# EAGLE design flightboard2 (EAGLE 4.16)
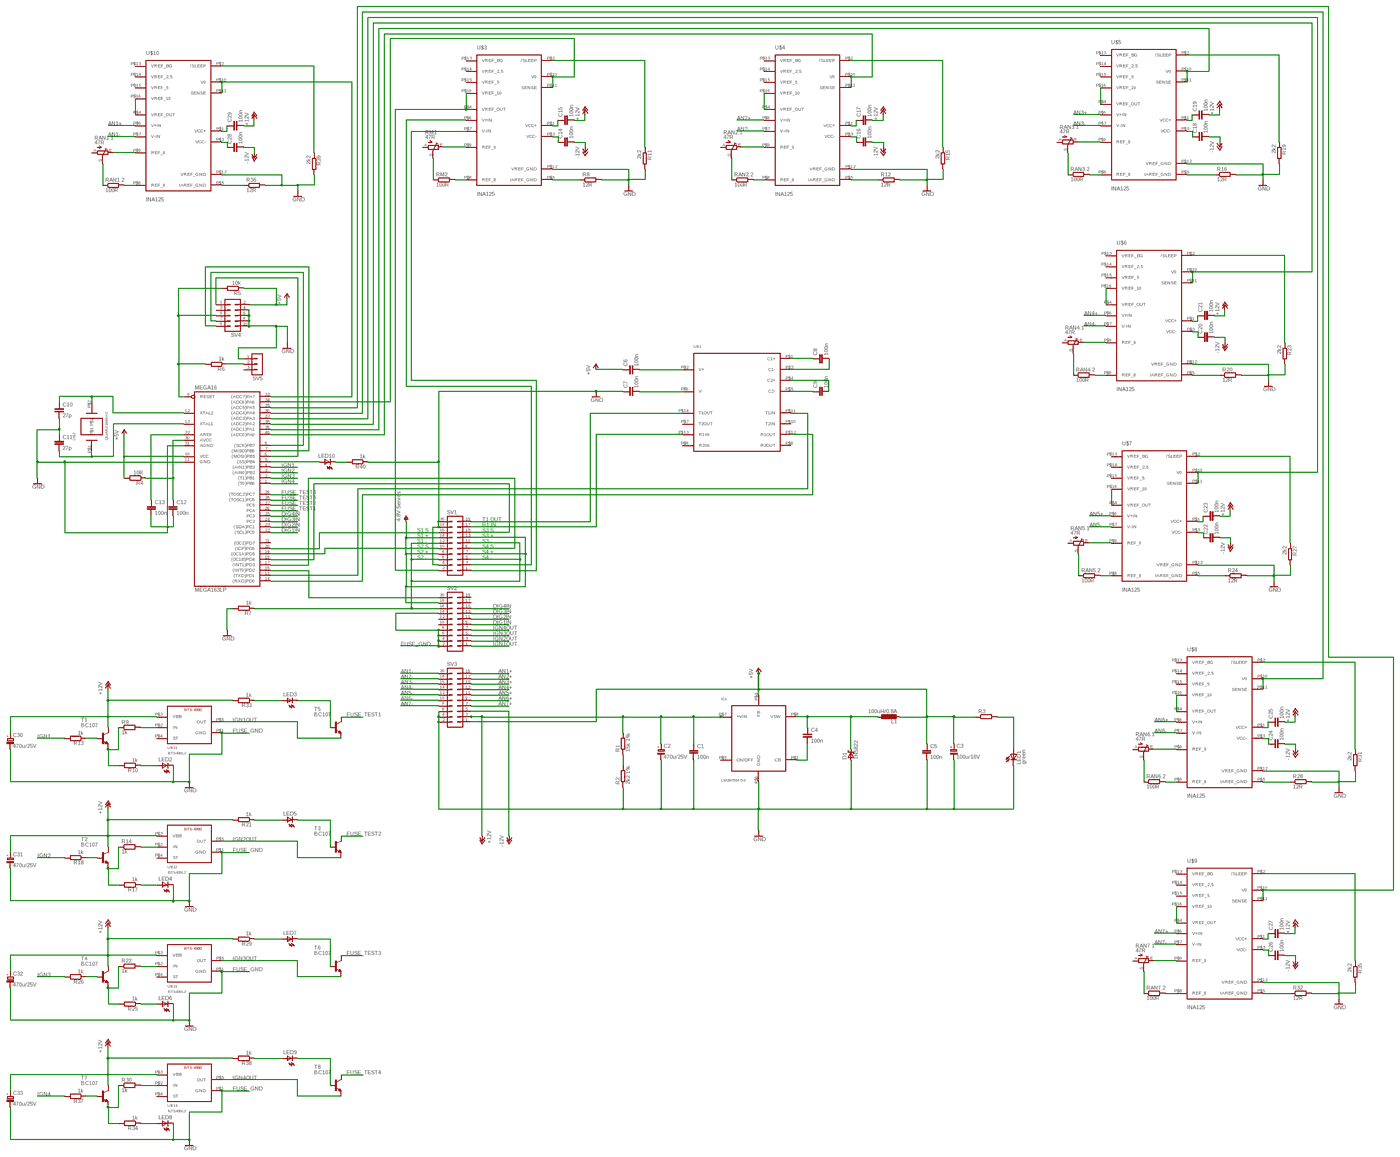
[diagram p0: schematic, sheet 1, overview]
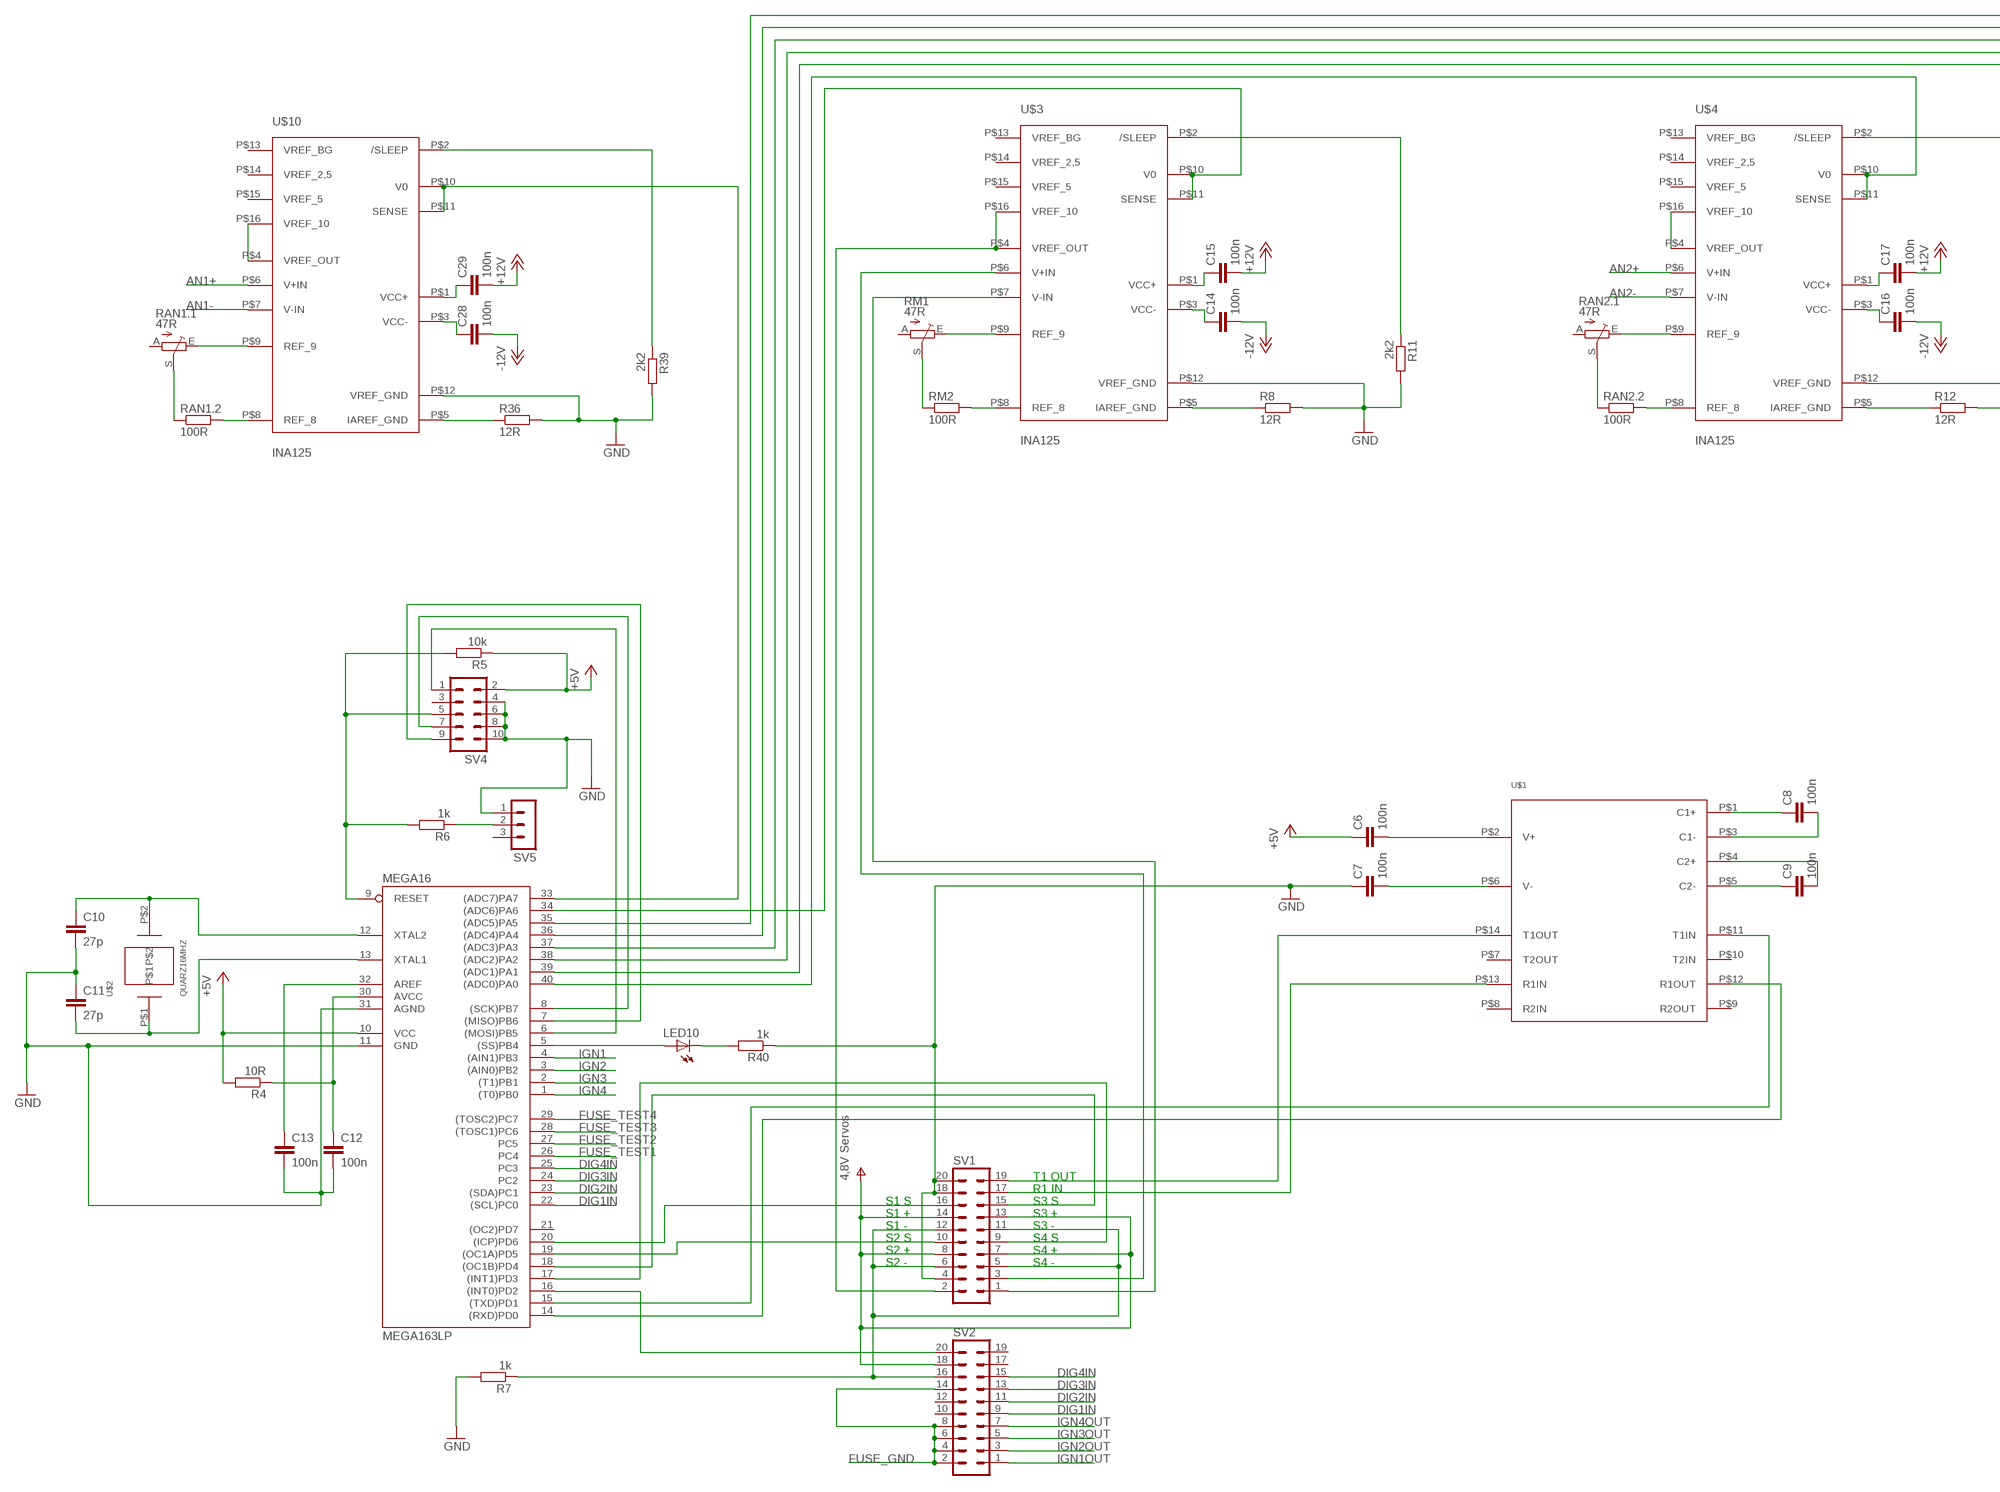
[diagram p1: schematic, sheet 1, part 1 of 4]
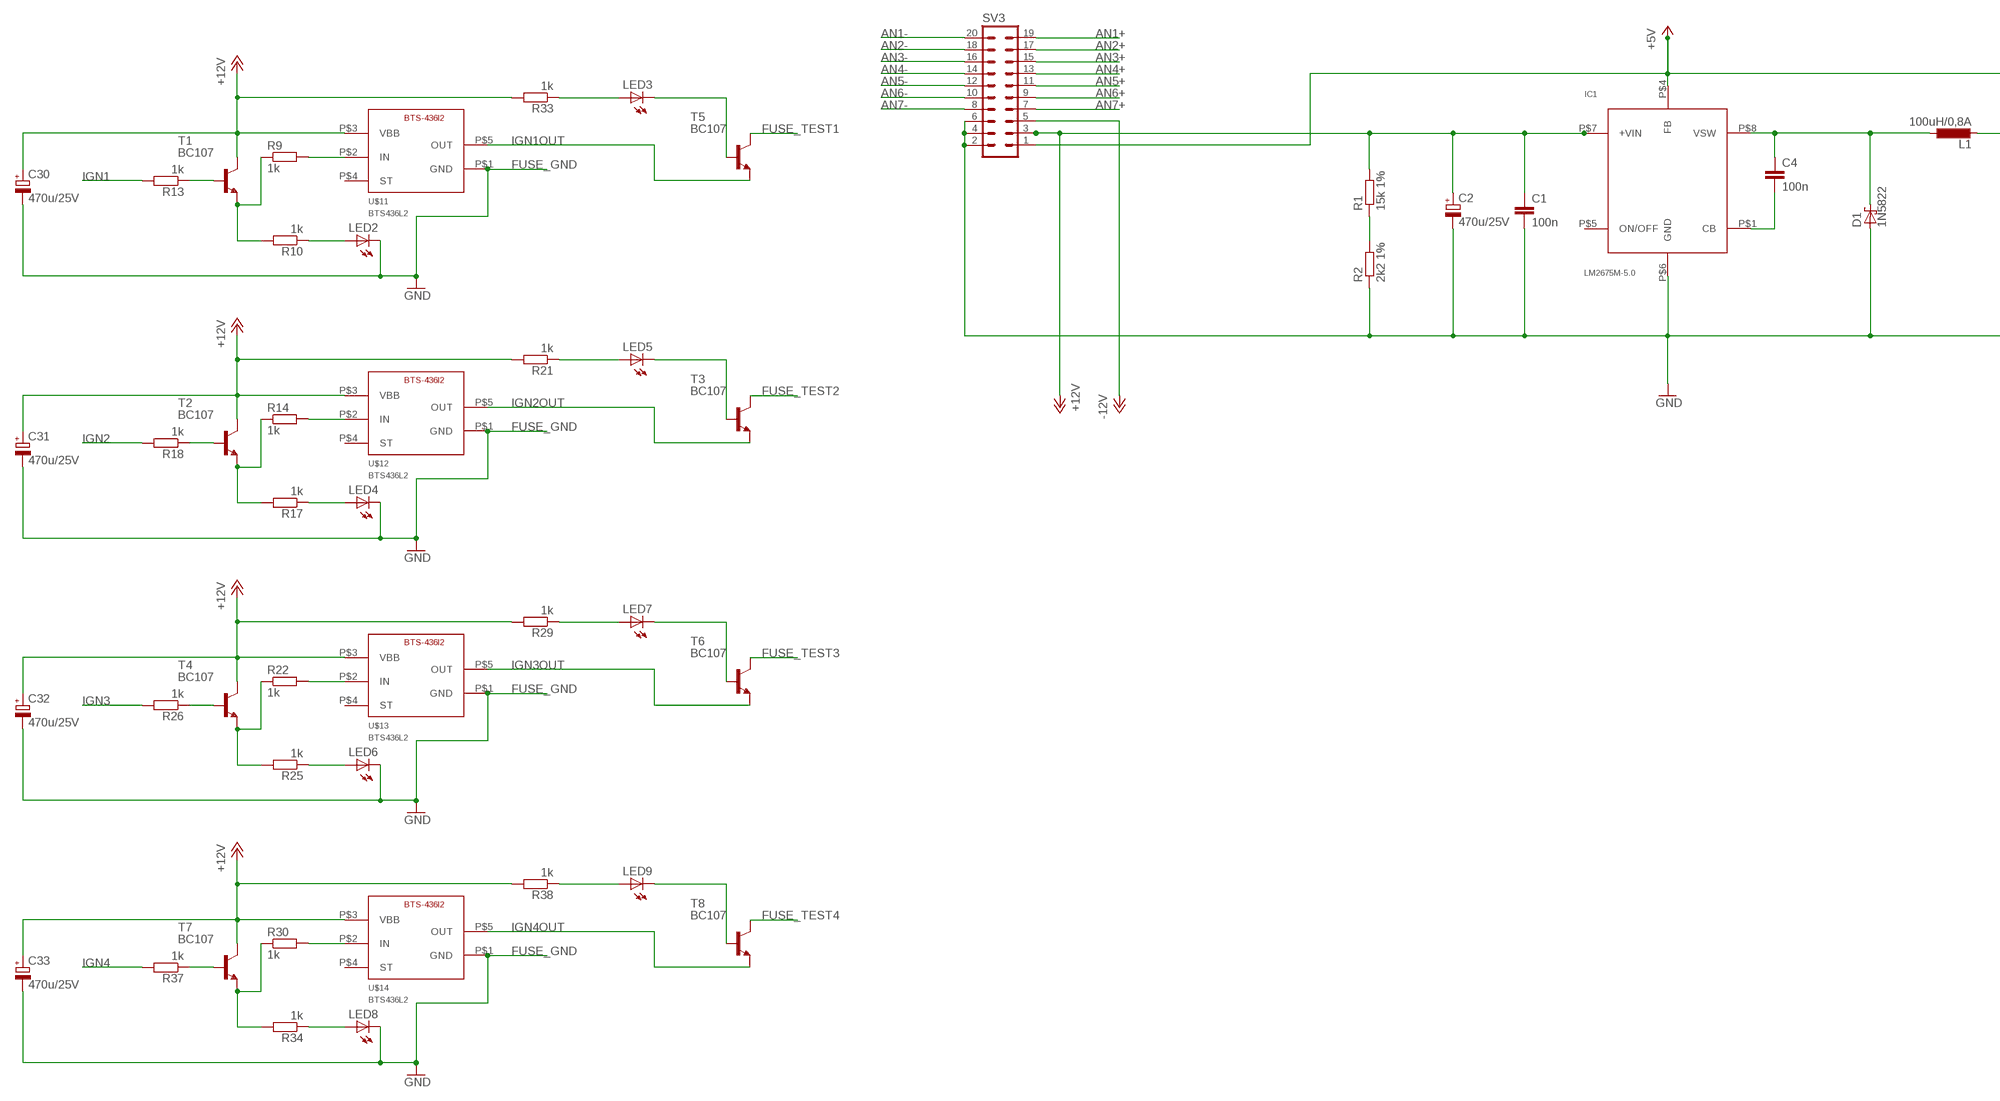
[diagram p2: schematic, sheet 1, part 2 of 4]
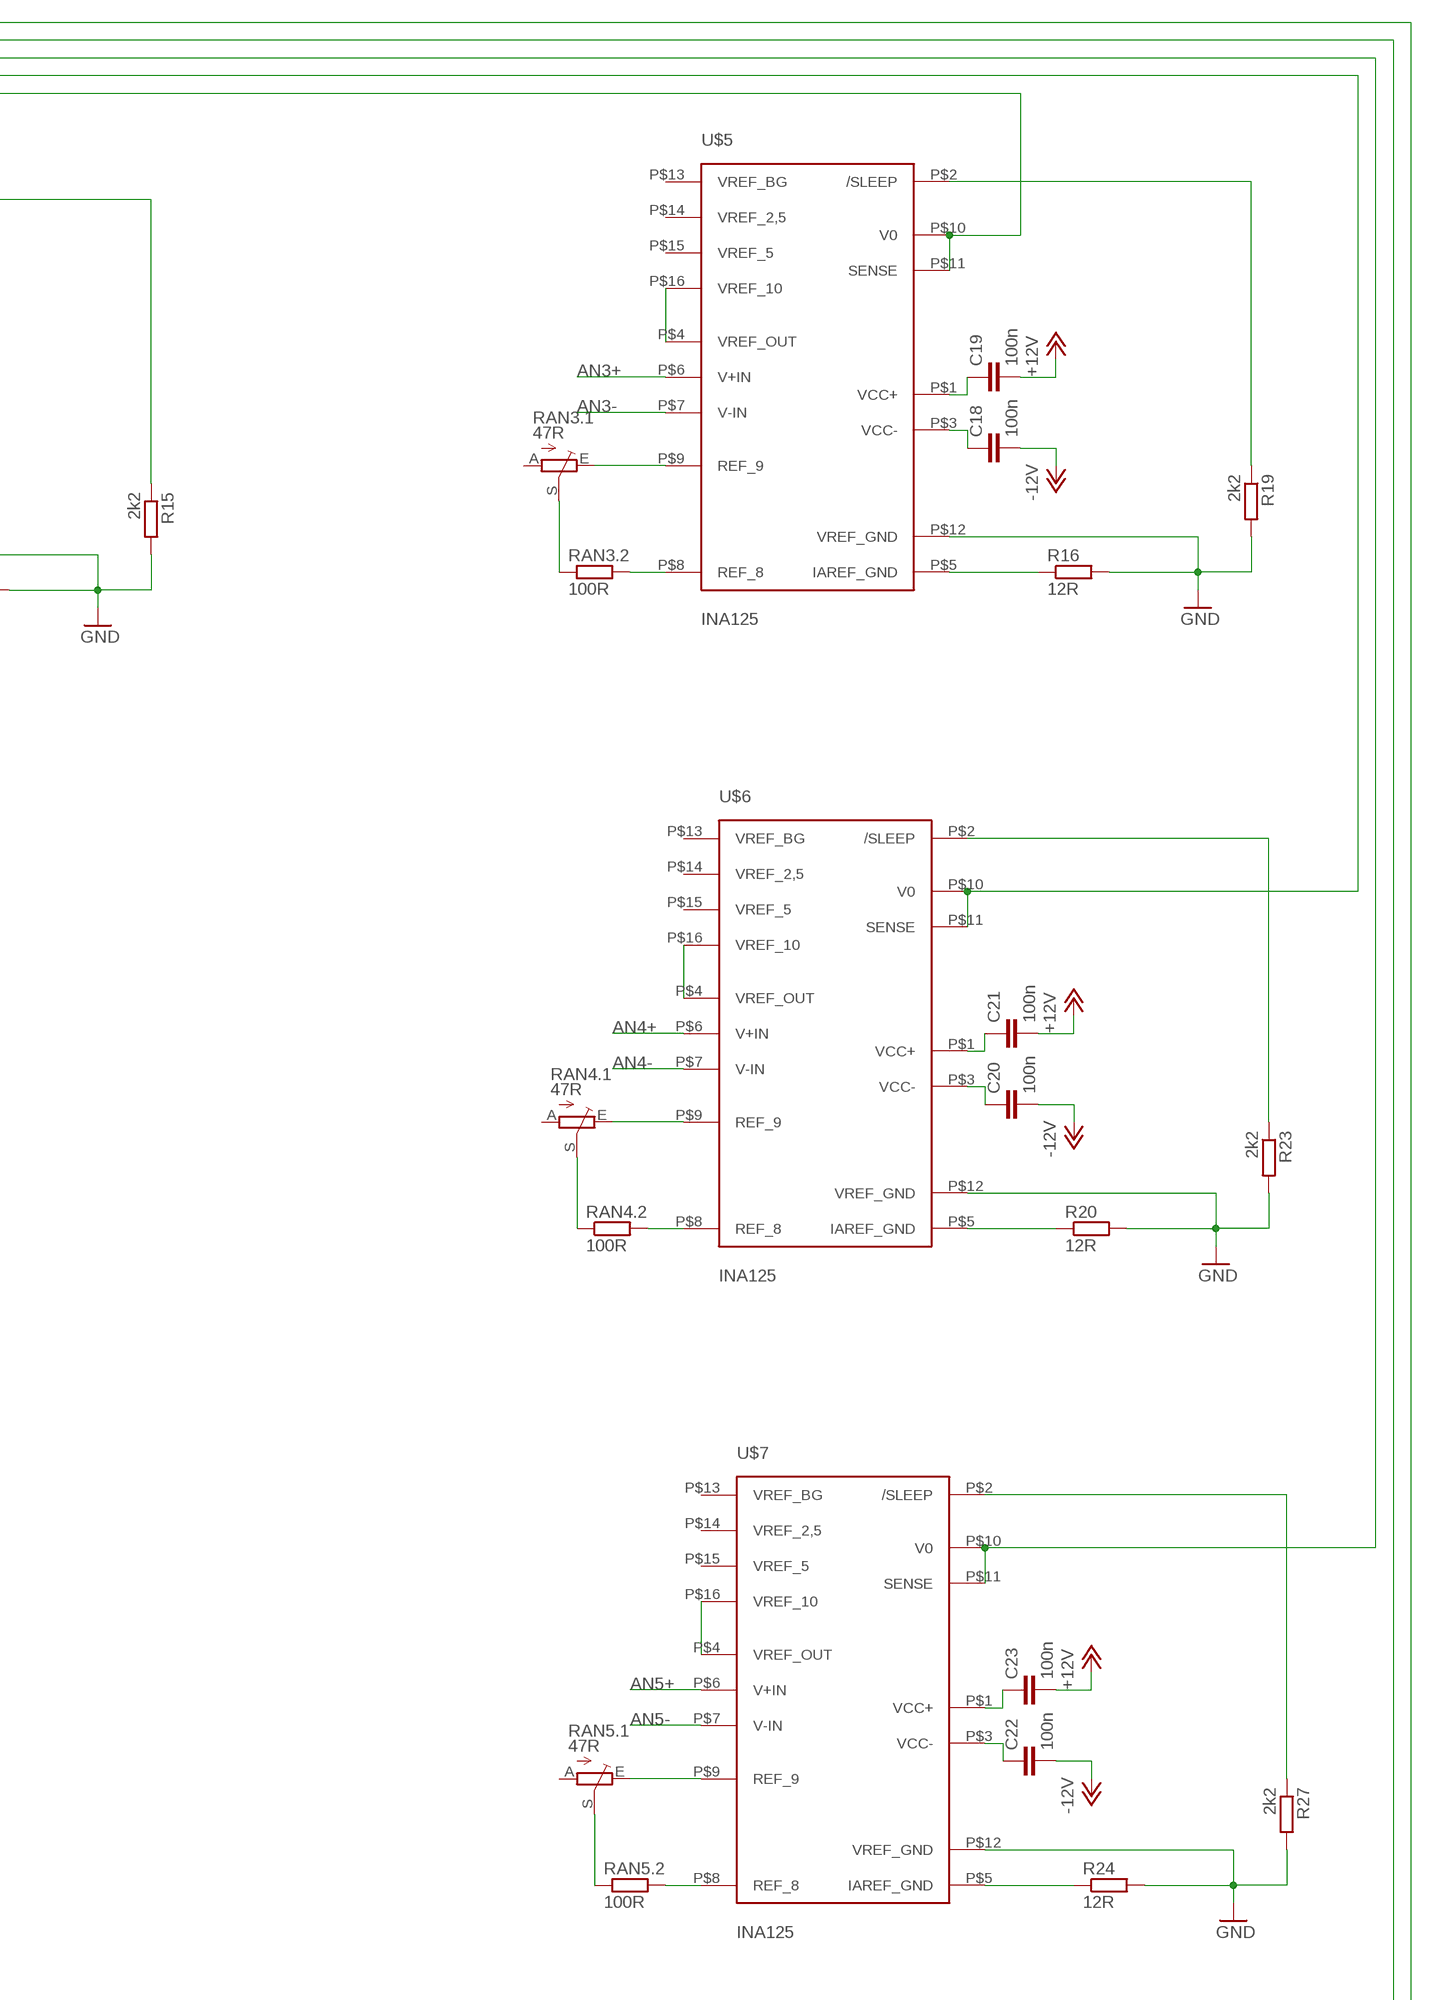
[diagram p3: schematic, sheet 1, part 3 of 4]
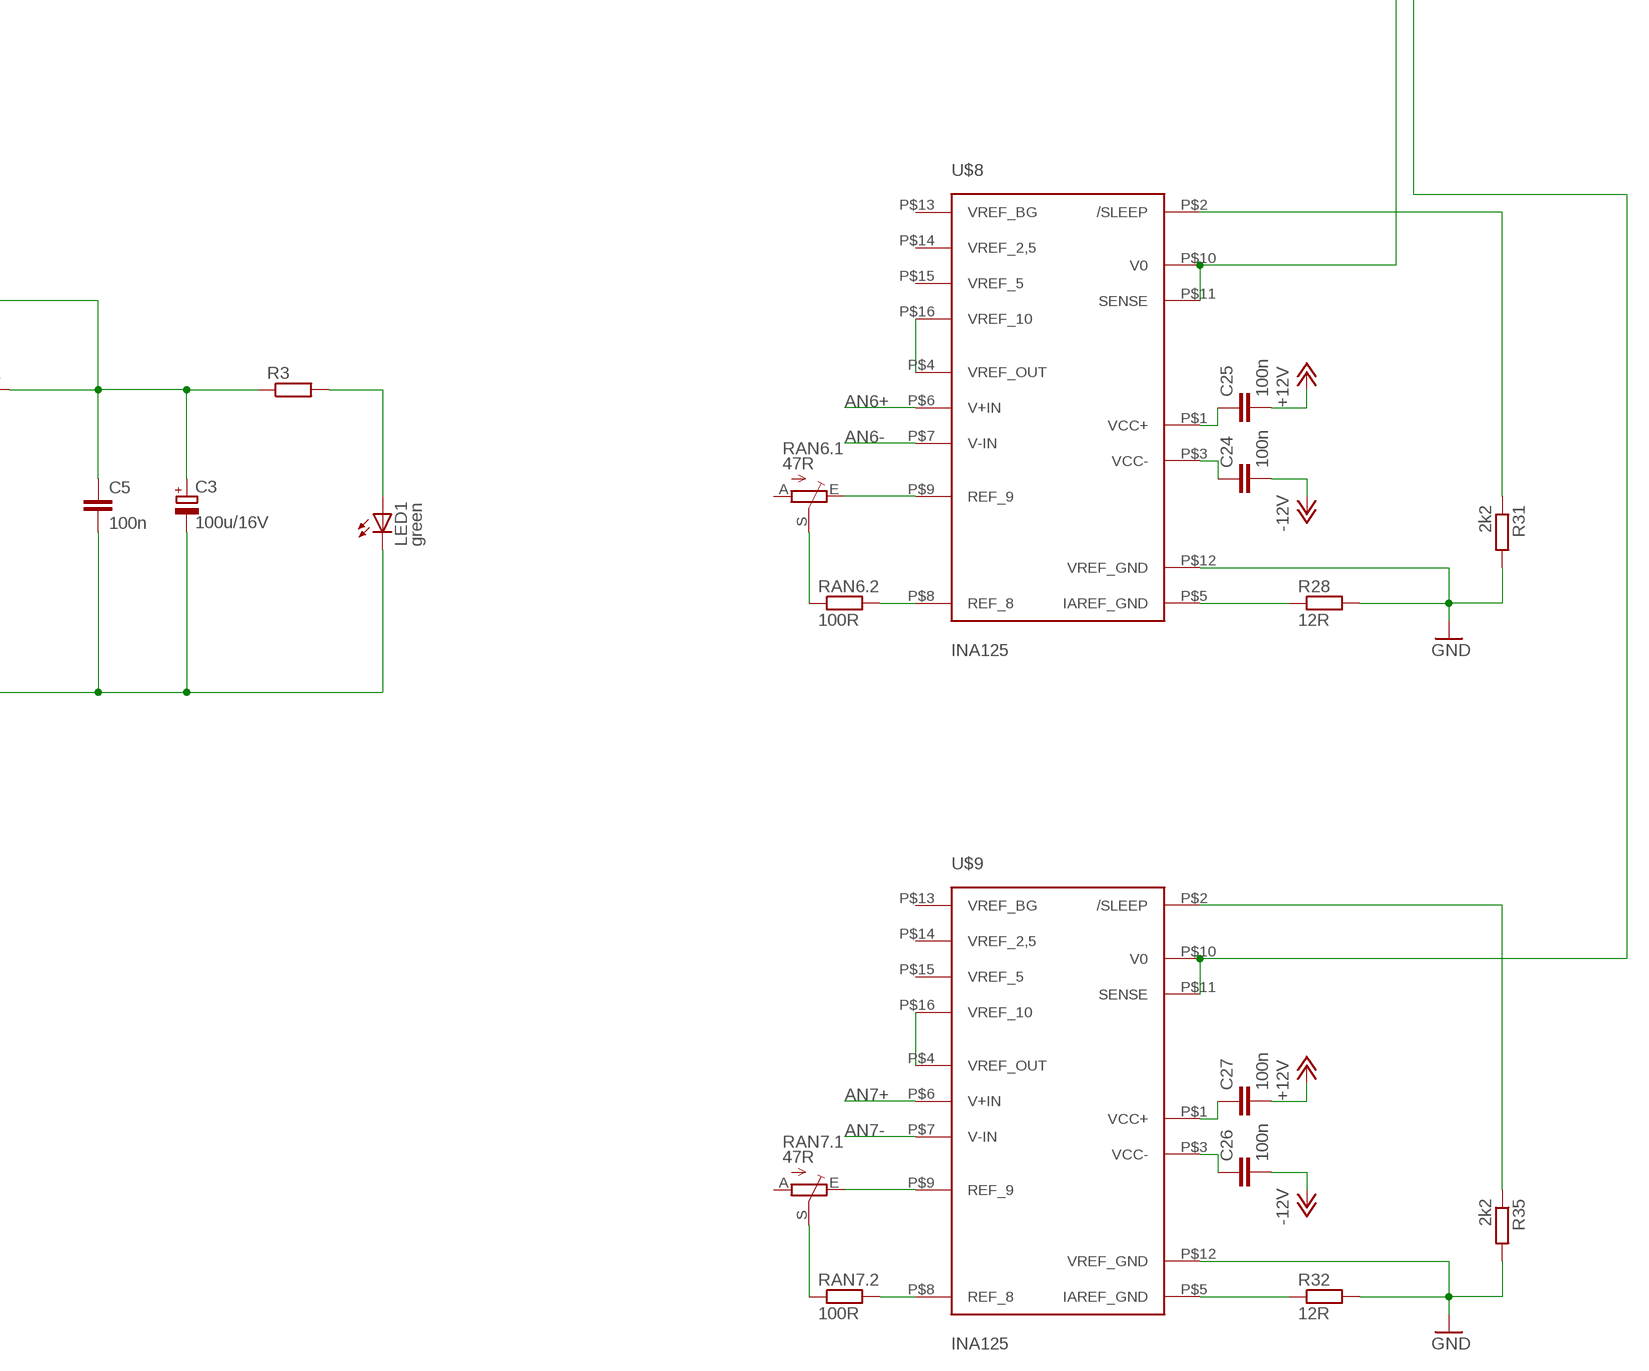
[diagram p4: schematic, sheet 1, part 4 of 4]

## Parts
C1  100n  C-EU025-024X044  [C025-024X044]
C2  470u/25V  CPOL-EUE3.5-10  [E3,5-10]
C3  100u/16V  CPOL-EUE2.5-5  [E2,5-5]
C4  100n  C-EU025-024X044  [C025-024X044]
C5  100n  C-EU025-024X044  [C025-024X044]
C6  100n  C-EU025-024X044  [C025-024X044]
C7  100n  C-EU025-024X044  [C025-024X044]
C8  100n  C-EU025-024X044  [C025-024X044]
C9  100n  C-EU025-024X044  [C025-024X044]
C10  27p  C-EU025-024X044  [C025-024X044]
C11  27p  C-EU025-024X044  [C025-024X044]
C12  100n  C-EU025-024X044  [C025-024X044]
C13  100n  C-EU025-024X044  [C025-024X044]
C14  100n  C-EU025-024X044  [C025-024X044]
C15  100n  C-EU025-024X044  [C025-024X044]
C16  100n  C-EU025-024X044  [C025-024X044]
C17  100n  C-EU025-024X044  [C025-024X044]
C18  100n  C-EU025-024X044  [C025-024X044]
C19  100n  C-EU025-024X044  [C025-024X044]
C20  100n  C-EU025-024X044  [C025-024X044]
C21  100n  C-EU025-024X044  [C025-024X044]
C22  100n  C-EU025-024X044  [C025-024X044]
C23  100n  C-EU025-024X044  [C025-024X044]
C24  100n  C-EU025-024X044  [C025-024X044]
C25  100n  C-EU025-024X044  [C025-024X044]
C26  100n  C-EU025-024X044  [C025-024X044]
C27  100n  C-EU025-024X044  [C025-024X044]
C28  100n  C-EU025-024X044  [C025-024X044]
C29  100n  C-EU025-024X044  [C025-024X044]
C30  470u/25V  CPOL-EUE3.5-10  [E3,5-10]
C31  470u/25V  CPOL-EUE3.5-10  [E3,5-10]
C32  470u/25V  CPOL-EUE3.5-10  [E3,5-10]
C33  470u/25V  CPOL-EUE3.5-10  [E3,5-10]
D1  1N5822  1N5908  [C4111-15]
IC1  LM2675M-5.0  [DIL-8]
L1  100uH/0,8A  L-EU0207/5V  [0207/5V]
LED1  green  LED3MM  [LED3MM]
LED2  LED3MM  [LED3MM]
LED3  LED3MM  [LED3MM]
LED4  LED3MM  [LED3MM]
LED5  LED3MM  [LED3MM]
LED6  LED3MM  [LED3MM]
LED7  LED3MM  [LED3MM]
LED8  LED3MM  [LED3MM]
LED9  LED3MM  [LED3MM]
LED10  LED3MM  [LED3MM]
MEGA16  MEGA163LP  [DIL40]
R1  15k 1%  R-EU_0207/10  [0207/10]
R2  2k2 1%  R-EU_0207/10  [0207/10]
R3  R-EU_0207/10  [0207/10]
R4  10R  R-EU_0309/10  [0309/10]
R5  10k  R-EU_0207/10  [0207/10]
R6  1k  R-EU_0207/10  [0207/10]
R7  1k  R-EU_0207/10  [0207/10]
R8  12R  R-EU_0309/10  [0309/10]
R9  1k  R-EU_0207/10  [0207/10]
R10  1k  R-EU_0207/10  [0207/10]
R11  2k2  R-EU_0309/10  [0309/10]
R12  12R  R-EU_0309/10  [0309/10]
R13  1k  R-EU_0207/10  [0207/10]
R14  1k  R-EU_0207/10  [0207/10]
R15  2k2  R-EU_0309/10  [0309/10]
R16  12R  R-EU_0309/10  [0309/10]
R17  1k  R-EU_0207/10  [0207/10]
R18  1k  R-EU_0207/10  [0207/10]
R19  2k2  R-EU_0309/10  [0309/10]
R20  12R  R-EU_0309/10  [0309/10]
R21  1k  R-EU_0207/10  [0207/10]
R22  1k  R-EU_0207/10  [0207/10]
R23  2k2  R-EU_0309/10  [0309/10]
R24  12R  R-EU_0309/10  [0309/10]
R25  1k  R-EU_0207/10  [0207/10]
R26  1k  R-EU_0207/10  [0207/10]
R27  2k2  R-EU_0309/10  [0309/10]
R28  12R  R-EU_0309/10  [0309/10]
R29  1k  R-EU_0207/10  [0207/10]
R30  1k  R-EU_0207/10  [0207/10]
R31  2k2  R-EU_0309/10  [0309/10]
R32  12R  R-EU_0309/10  [0309/10]
R33  1k  R-EU_0207/10  [0207/10]
R34  1k  R-EU_0207/10  [0207/10]
R35  2k2  R-EU_0309/10  [0309/10]
R36  12R  R-EU_0309/10  [0309/10]
R37  1k  R-EU_0207/10  [0207/10]
R38  1k  R-EU_0207/10  [0207/10]
R39  2k2  R-EU_0309/10  [0309/10]
R40  1k  R-EU_0309/10  [0309/10]
RAN1.1  47R  TRIM_EU-B90P  [SP19L]
RAN1.2  100R  R-EU_0309/10  [0309/10]
RAN2.1  47R  TRIM_EU-B90P  [SP19L]
RAN2.2  100R  R-EU_0309/10  [0309/10]
RAN3.1  47R  TRIM_EU-B90P  [SP19L]
RAN3.2  100R  R-EU_0309/10  [0309/10]
RAN4.1  47R  TRIM_EU-B90P  [SP19L]
RAN4.2  100R  R-EU_0309/10  [0309/10]
RAN5.1  47R  TRIM_EU-B90P  [SP19L]
RAN5.2  100R  R-EU_0309/10  [0309/10]
RAN6.1  47R  TRIM_EU-B90P  [SP19L]
RAN6.2  100R  R-EU_0309/10  [0309/10]
RAN7.1  47R  TRIM_EU-B90P  [SP19L]
RAN7.2  100R  R-EU_0309/10  [0309/10]
RM1  47R  TRIM_EU-B90P  [SP19L]
RM2  100R  R-EU_0309/10  [0309/10]
SV1  MA10-2W  [MA10-2W]
SV2  MA10-2W  [MA10-2W]
SV3  MA10-2W  [MA10-2W]
SV4  MA05-2  [MA05-2]
SV5  MA03-1  [MA03-1]
T1  BC107  [TO18]
T2  BC107  [TO18]
T3  BC107  [TO18]
T4  BC107  [TO18]
T5  BC107  [TO18]
T6  BC107  [TO18]
T7  BC107  [TO18]
T8  BC107  [TO18]
U$1  MAX232  [DIL-16]
U$2  QUARZ16MHZ  [QUARZ16MHZ]
U$3  INA125  [DIL-16]
U$4  INA125  [DIL-16]
U$5  INA125  [DIL-16]
U$6  INA125  [DIL-16]
U$7  INA125  [DIL-16]
U$8  INA125  [DIL-16]
U$9  INA125  [DIL-16]
U$10  INA125  [DIL-16]
U$11  BTS436L2  [TO-GEHÄUSE]
U$12  BTS436L2  [TO-GEHÄUSE]
U$13  BTS436L2  [TO-GEHÄUSE]
U$14  BTS436L2  [TO-GEHÄUSE]

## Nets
+5V: C3.+ C5.1 C6.1 IC1.P$4(FB) L1.2 MEGA16.10(VCC) R3.1 R4.2 R5.1 SV3.1 SV4.2
+12V: C1.1 C2.+ C15.2 C17.2 C19.2 C21.2 C23.2 C25.2 C27.2 C29.2 C30.+ C31.+ C32.+ C33.+ IC1.P$7(+VIN) R1.2 R21.2 R29.2 R33.2 R38.2 SV3.3 T1.3(C) T2.3(C) T4.3(C) T7.3(C) U$11.P$3(VBB) U$12.P$3(VBB) U$13.P$3(VBB) U$14.P$3(VBB)
-12V: C14.2 C16.2 C18.2 C20.2 C22.2 C24.2 C26.2 C28.2 SV3.5
AMP1: U$10.P$4(VREF_OUT) U$10.P$16(VREF_10)
AN1+: SV3.19 U$10.P$6(V+IN)
AN1-: SV3.20 U$10.P$7(V-IN)
AN2+: SV3.17 U$4.P$6(V+IN)
AN2-: SV3.18 U$4.P$7(V-IN)
AN3+: SV3.15 U$5.P$6(V+IN)
AN3-: SV3.16 U$5.P$7(V-IN)
AN4+: SV3.13 U$6.P$6(V+IN)
AN4-: SV3.14 U$6.P$7(V-IN)
AN5+: SV3.11 U$7.P$6(V+IN)
AN5-: SV3.12 U$7.P$7(V-IN)
AN6+: SV3.9 U$8.P$6(V+IN)
AN6-: SV3.10 U$8.P$7(V-IN)
AN7+: SV3.7 U$9.P$6(V+IN)
AN7-: SV3.8 U$9.P$7(V-IN)
DIG1IN: MEGA16.22((SCL)PC0) SV2.9
DIG2IN: MEGA16.23((SDA)PC1) SV2.11
DIG3IN: MEGA16.24(PC2) SV2.13
DIG4IN: MEGA16.25(PC3) SV2.15
FUSE_GND: C1.2 C2.- C3.- C5.2 C7.1 C10.2 C11.1 C12.2 C13.2 C30.- C31.- C32.- C33.- D1.A IC1.P$6(GND) LED1.K(C) LED2.K(C) LED4.K(C) LED6.K(C) LED8.K(C) MEGA16.11(GND) MEGA16.31(AGND) R2.1 R7.2 R8.2 R11.2 R12.2 R15.2 R16.2 R19.2 R20.2 R23.2 R24.2 R27.2 R28.2 R31.2 R32.2 R35.2 R36.2 R39.2 R40.1 SV1.4 SV1.18 SV1.20 SV2.2 SV2.4 SV2.6 SV2.8 SV2.14 SV3.2 SV3.4 SV3.6 SV4.4 SV4.6 SV4.8 SV4.10 SV5.1 U$3.P$12(VREF_GND) U$4.P$12(VREF_GND) U$5.P$12(VREF_GND) U$6.P$12(VREF_GND) U$7.P$12(VREF_GND) U$8.P$12(VREF_GND) U$9.P$12(VREF_GND) U$10.P$12(VREF_GND) U$11.P$1(GND) U$12.P$1(GND) U$13.P$1(GND) U$14.P$1(GND) ; supply symbol labelled GND
FUSE_TEST1: MEGA16.26(PC4) T5.3(C)
FUSE_TEST2: MEGA16.27(PC5) T3.3(C)
FUSE_TEST3: MEGA16.28((TOSC1)PC6) T6.3(C)
FUSE_TEST4: MEGA16.29((TOSC2)PC7) T8.3(C)
IGN1: MEGA16.4((AIN1)PB3) R13.2
IGN1OUT: SV2.1 T5.1(E) U$11.P$5(OUT)
IGN2: MEGA16.3((AIN0)PB2) R18.2
IGN2OUT: SV2.3 T3.1(E) U$12.P$5(OUT)
IGN3: MEGA16.2((T1)PB1) R26.2
IGN3OUT: SV2.5 T6.1(E) U$13.P$5(OUT)
IGN4: MEGA16.1((T0)PB0) R37.2
IGN4OUT: SV2.7 T8.1(E) U$14.P$5(OUT)
N$1: R1.1 R2.2
N$2: C4.2 IC1.P$1(CB)
N$3: C4.1 D1.C IC1.P$8(VSW) L1.1
N$4: C6.2 U$1.P$2(V+)
N$5: LED1.A R3.2
N$6: C7.2 U$1.P$6(V-)
N$7: C9.1 U$1.P$5(C2-)
N$8: C8.1 U$1.P$1(C1+)
N$9: C8.2 U$1.P$3(C1-)
N$10: C9.2 U$1.P$4(C2+)
N$11: SV1.17 U$1.P$13(R1IN)
N$12: SV1.19 U$1.P$14(T1OUT)
N$13: MEGA16.14((RXD)PD0) U$1.P$12(R1OUT)
N$14: MEGA16.15((TXD)PD1) U$1.P$11(T1IN)
N$15: C11.2 MEGA16.13(XTAL1) U$2.P$1
N$16: C10.1 MEGA16.12(XTAL2) U$2.P$2
N$17: MEGA16.17((INT1)PD3) SV1.9
N$18: C12.1 MEGA16.30(AVCC) R4.1
N$19: C13.1 MEGA16.32(AREF)
N$20: MEGA16.9(RESET) R5.2 R6.2 SV4.5
N$21: MEGA16.16((INT0)PD2) SV2.20
N$22: R6.1 SV5.2
N$23: MEGA16.20((ICP)PD6) SV1.16
N$24: MEGA16.19((OC1A)PD5) SV1.10
N$25: R7.1 SV1.5 SV1.6 SV1.11 SV1.12 SV2.16
N$26: MEGA16.18((OC1B)PD4) SV1.15
N$27: C14.1 U$3.P$3(VCC-)
N$28: C15.1 U$3.P$1(VCC+)
N$29: MEGA16.34((ADC6)PA6) U$3.P$10(V0) U$3.P$11(SENSE)
N$30: RM2.2 U$3.P$8(REF_8)
N$31: RM1.E U$3.P$9(REF_9)
N$32: RM1.S RM2.1
N$33: SV1.2 U$3.P$4(VREF_OUT) U$3.P$16(VREF_10)
N$34: R11.1 U$3.P$2(/SLEEP)
N$35: C16.1 U$4.P$3(VCC-)
N$36: SV1.3 U$3.P$6(V+IN)
N$37: SV1.1 U$3.P$7(V-IN)
N$38: C17.1 U$4.P$1(VCC+)
N$39: MEGA16.40((ADC0)PA0) U$4.P$10(V0) U$4.P$11(SENSE)
N$40: RAN2.2.2 U$4.P$8(REF_8)
N$41: RAN2.1.E U$4.P$9(REF_9)
N$42: RAN2.1.S RAN2.2.1
N$43: R15.1 U$4.P$2(/SLEEP)
N$44: U$4.P$4(VREF_OUT) U$4.P$16(VREF_10)
N$45: R9.2 U$11.P$2(IN)
N$47: C18.1 U$5.P$3(VCC-)
N$48: C19.1 U$5.P$1(VCC+)
N$49: C26.1 U$9.P$3(VCC-)
N$50: RAN3.2.2 U$5.P$8(REF_8)
N$51: RAN3.1.E U$5.P$9(REF_9)
N$52: RAN3.1.S RAN3.2.1
N$53: R19.1 U$5.P$2(/SLEEP)
N$54: U$5.P$4(VREF_OUT) U$5.P$16(VREF_10)
N$55: U$6.P$4(VREF_OUT) U$6.P$16(VREF_10)
N$56: U$7.P$4(VREF_OUT) U$7.P$16(VREF_10)
N$57: C20.1 U$6.P$3(VCC-)
N$58: C21.1 U$6.P$1(VCC+)
N$59: C27.1 U$9.P$1(VCC+)
N$60: RAN4.2.2 U$6.P$8(REF_8)
N$61: RAN4.1.E U$6.P$9(REF_9)
N$62: RAN4.1.S RAN4.2.1
N$63: R23.1 U$6.P$2(/SLEEP)
N$64: U$8.P$4(VREF_OUT) U$8.P$16(VREF_10)
N$65: U$9.P$4(VREF_OUT) U$9.P$16(VREF_10)
N$66: R14.2 U$12.P$2(IN)
N$67: C22.1 U$7.P$3(VCC-)
N$68: C23.1 U$7.P$1(VCC+)
N$69: C28.1 U$10.P$3(VCC-)
N$70: RAN5.2.2 U$7.P$8(REF_8)
N$71: RAN5.1.E U$7.P$9(REF_9)
N$72: RAN5.1.S RAN5.2.1
N$73: R27.1 U$7.P$2(/SLEEP)
N$74: R9.1 R10.2 T1.1(E)
N$75: R13.1 T1.2(B)
N$76: LED3.K(C) T5.2(B)
N$77: C24.1 U$8.P$3(VCC-)
N$78: C25.1 U$8.P$1(VCC+)
N$79: C29.1 U$10.P$1(VCC+)
N$80: RAN6.2.2 U$8.P$8(REF_8)
N$81: RAN6.1.E U$8.P$9(REF_9)
N$82: RAN6.1.S RAN6.2.1
N$83: R31.1 U$8.P$2(/SLEEP)
N$84: R14.1 R17.2 T2.1(E)
N$85: R18.1 T2.2(B)
N$86: LED4.A R17.1
N$87: RAN7.2.2 U$9.P$8(REF_8)
N$88: MEGA16.39((ADC1)PA1) U$5.P$10(V0) U$5.P$11(SENSE)
N$89: MEGA16.38((ADC2)PA2) U$6.P$10(V0) U$6.P$11(SENSE)
N$90: MEGA16.37((ADC3)PA3) U$7.P$10(V0) U$7.P$11(SENSE)
N$91: MEGA16.36((ADC4)PA4) U$8.P$10(V0) U$8.P$11(SENSE)
N$92: MEGA16.35((ADC5)PA5) U$9.P$10(V0) U$9.P$11(SENSE)
N$93: RAN7.1.E U$9.P$9(REF_9)
N$94: RAN7.1.S RAN7.2.1
N$95: R35.1 U$9.P$2(/SLEEP)
N$96: LED5.A R21.1
N$97: LED5.K(C) T3.2(B)
N$98: R22.2 U$13.P$2(IN)
N$99: MEGA16.33((ADC7)PA7) U$10.P$10(V0) U$10.P$11(SENSE)
N$100: RAN1.2.2 U$10.P$8(REF_8)
N$101: RAN1.1.E U$10.P$9(REF_9)
N$102: RAN1.1.S RAN1.2.1
N$103: R39.1 U$10.P$2(/SLEEP)
N$104: R22.1 R25.2 T4.1(E)
N$105: R26.1 T4.2(B)
N$106: LED6.A R25.1
N$107: MEGA16.8((SCK)PB7) SV4.7
N$108: MEGA16.6((MOSI)PB5) SV4.1
N$109: MEGA16.7((MISO)PB6) SV4.9
N$110: LED7.A R29.1
N$111: LED7.K(C) T6.2(B)
N$112: R36.1 U$10.P$5(IAREF_GND)
N$113: R8.1 U$3.P$5(IAREF_GND)
N$114: R12.1 U$4.P$5(IAREF_GND)
N$115: R16.1 U$5.P$5(IAREF_GND)
N$116: R20.1 U$6.P$5(IAREF_GND)
N$117: R24.1 U$7.P$5(IAREF_GND)
N$118: R28.1 U$8.P$5(IAREF_GND)
N$119: R32.1 U$9.P$5(IAREF_GND)
N$120: LED2.A R10.1
N$121: LED3.A R33.1
N$122: R30.2 U$14.P$2(IN)
N$123: R30.1 R34.2 T7.1(E)
N$124: R37.1 T7.2(B)
N$125: LED8.A R34.1
N$126: LED9.A R38.1
N$127: LED9.K(C) T8.2(B)
N$128: LED10.A MEGA16.5((SS)PB4)
N$129: LED10.K(C) R40.2
V+: SV1.7 SV1.8 SV1.13 SV1.14 SV2.18 ; supply symbol labelled 4,8V Servos
Unconnected: IC1.P$5(ON/OFF) MEGA16.21((OC2)PD7) RAN1.1.A RAN2.1.A RAN3.1.A RAN4.1.A RAN5.1.A RAN6.1.A RAN7.1.A RM1.A SV2.10 SV2.12 SV2.17 SV2.19 SV4.3 SV5.3 U$1.P$7(T2OUT) U$1.P$8(R2IN) U$1.P$9(R2OUT) U$1.P$10(T2IN) U$3.P$13(VREF_BG) U$3.P$14(VREF_2,5) U$3.P$15(VREF_5) U$4.P$13(VREF_BG) U$4.P$14(VREF_2,5) U$4.P$15(VREF_5) U$5.P$13(VREF_BG) U$5.P$14(VREF_2,5) U$5.P$15(VREF_5) U$6.P$13(VREF_BG) U$6.P$14(VREF_2,5) U$6.P$15(VREF_5) U$7.P$13(VREF_BG) U$7.P$14(VREF_2,5) U$7.P$15(VREF_5) U$8.P$13(VREF_BG) U$8.P$14(VREF_2,5) U$8.P$15(VREF_5) U$9.P$13(VREF_BG) U$9.P$14(VREF_2,5) U$9.P$15(VREF_5) U$10.P$13(VREF_BG) U$10.P$14(VREF_2,5) U$10.P$15(VREF_5) U$11.P$4(ST) U$12.P$4(ST) U$13.P$4(ST) U$14.P$4(ST)

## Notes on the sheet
- T1 OUT
- R1 IN
- S1 S | S3 S
- S1 + | S3 +
- S1 - | S3 -
- S2 S | S4 S
- S2 + | S4 +
- S2 - | S4 -

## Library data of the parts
C1 C4-C29 = rcl:C-EU: CAPACITOR, European symbol
C2 C3 C30-C33 = rcl:CPOL-EU: POLARIZED CAPACITOR, European symbol
D1 = diode:1N5908: DIODE
IC1 = eigene:LM2675M-5.0
L1 = rcl:L-EU: INDUCTOR, European symbol
LED1-LED10 = led:LED: LED
MEGA16 = atmel:MEGA163*P: MICROCONTROLLER 16 Kbytes FLASH, 1 Kbytes EEPROM 1 Kbytes SRAM UART 8-channel 10 bit ADC hardware multiplier
R1-R40 RAN1.2 RAN2.2 RAN3.2 RAN4.2 RAN5.2 RAN6.2 RAN7.2 RM2 = rcl:R-EU_: RESISTOR, European symbol
RAN1.1 RAN2.1 RAN3.1 RAN4.1 RAN5.1 RAN6.1 RAN7.1 RM1 = pot:TRIM_EU-: POTENTIOMETER
SV1-SV3 = con-lstb:MA10-2W: PIN HEADER
SV4 = con-lstb:MA05-2: PIN HEADER
SV5 = con-lstb:MA03-1: PIN HEADER
T1-T8 = transistor:BC107: NPN TRANSISTOR
U$1 = eigene:MAX232
U$2 = eigene:QUARZ16MHZ
U$3-U$10 = eigene:INA125
U$11-U$14 = eigene:BTS436L2

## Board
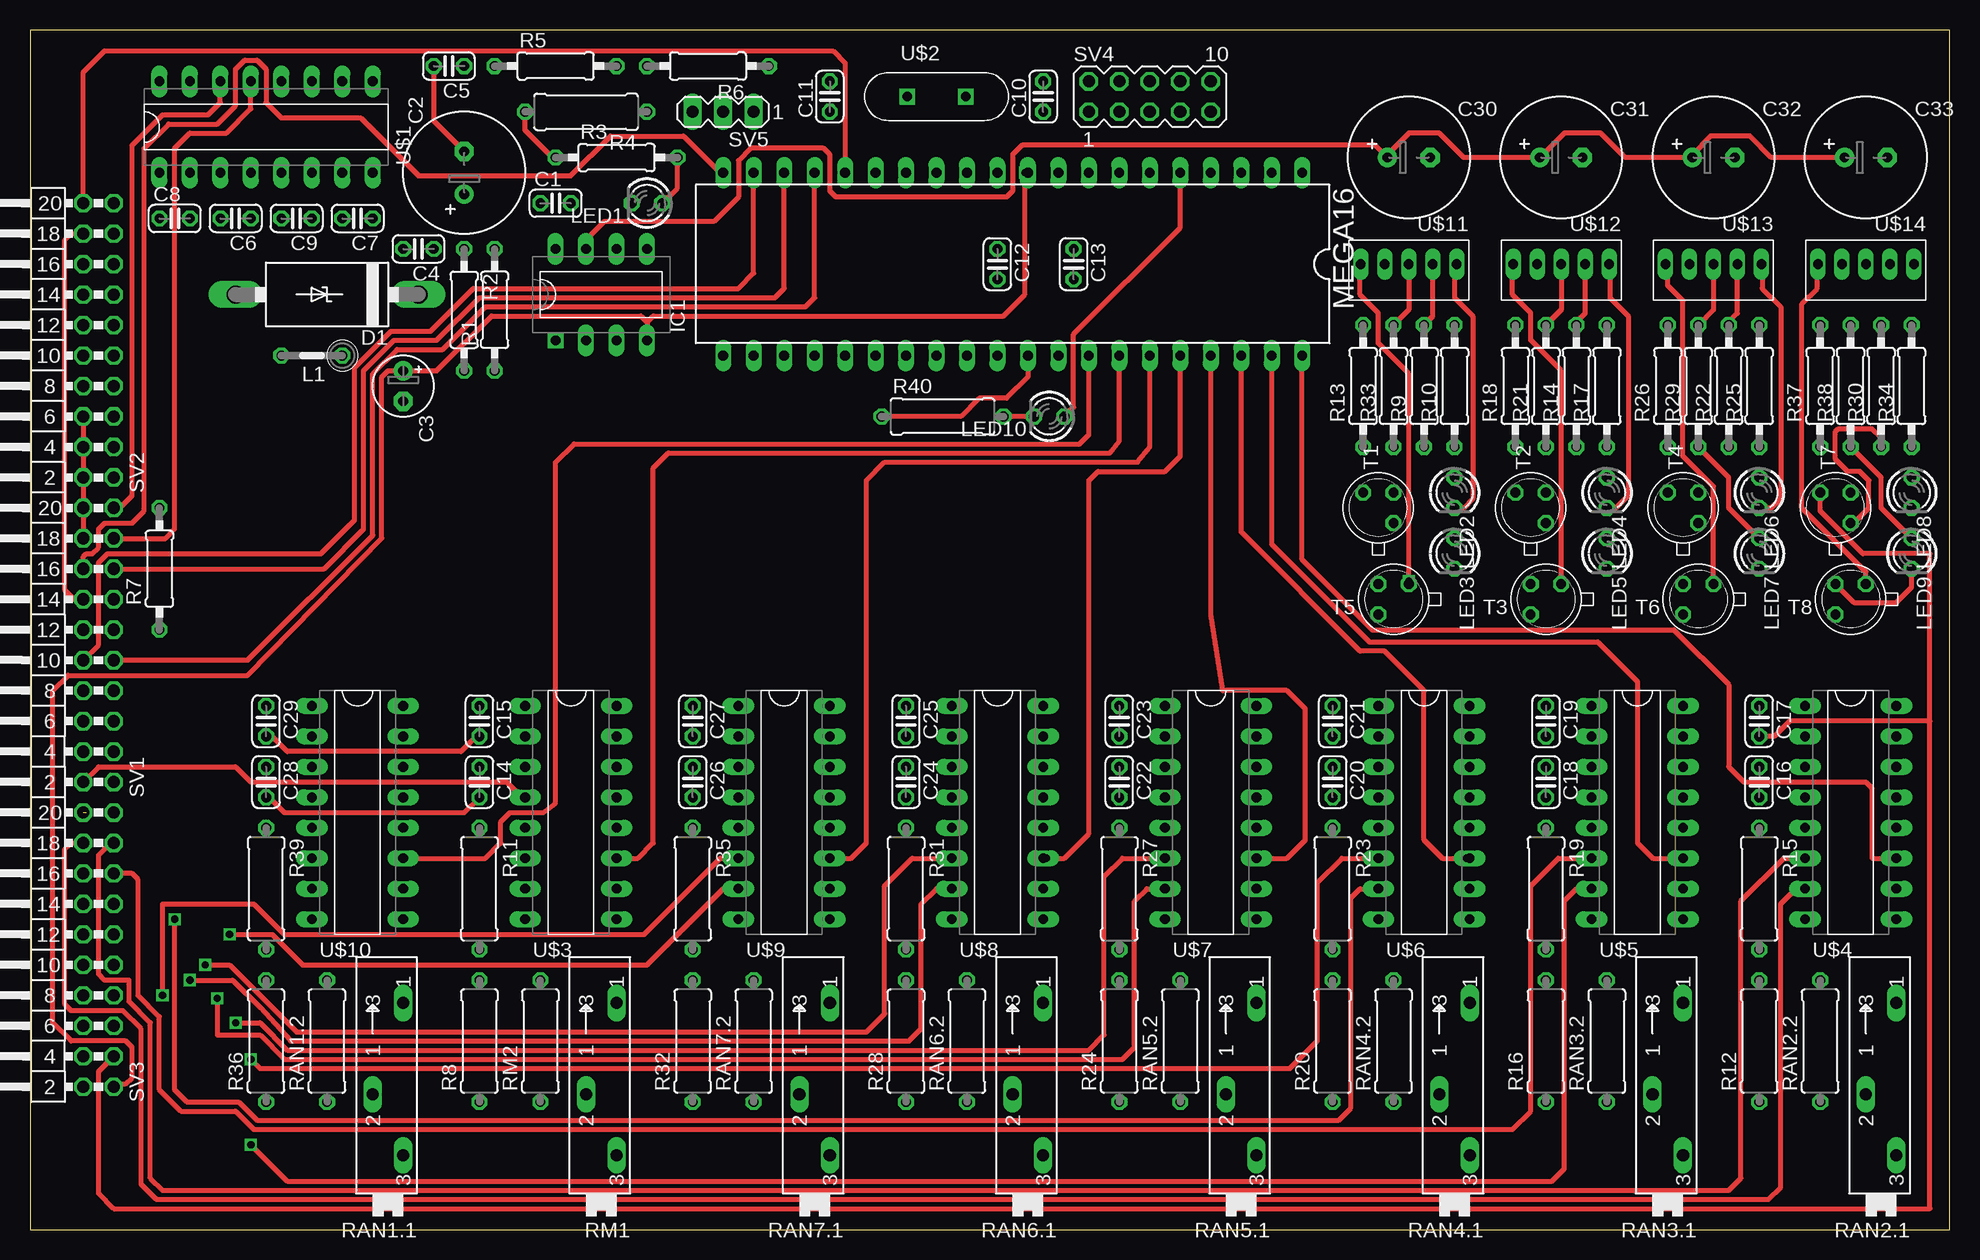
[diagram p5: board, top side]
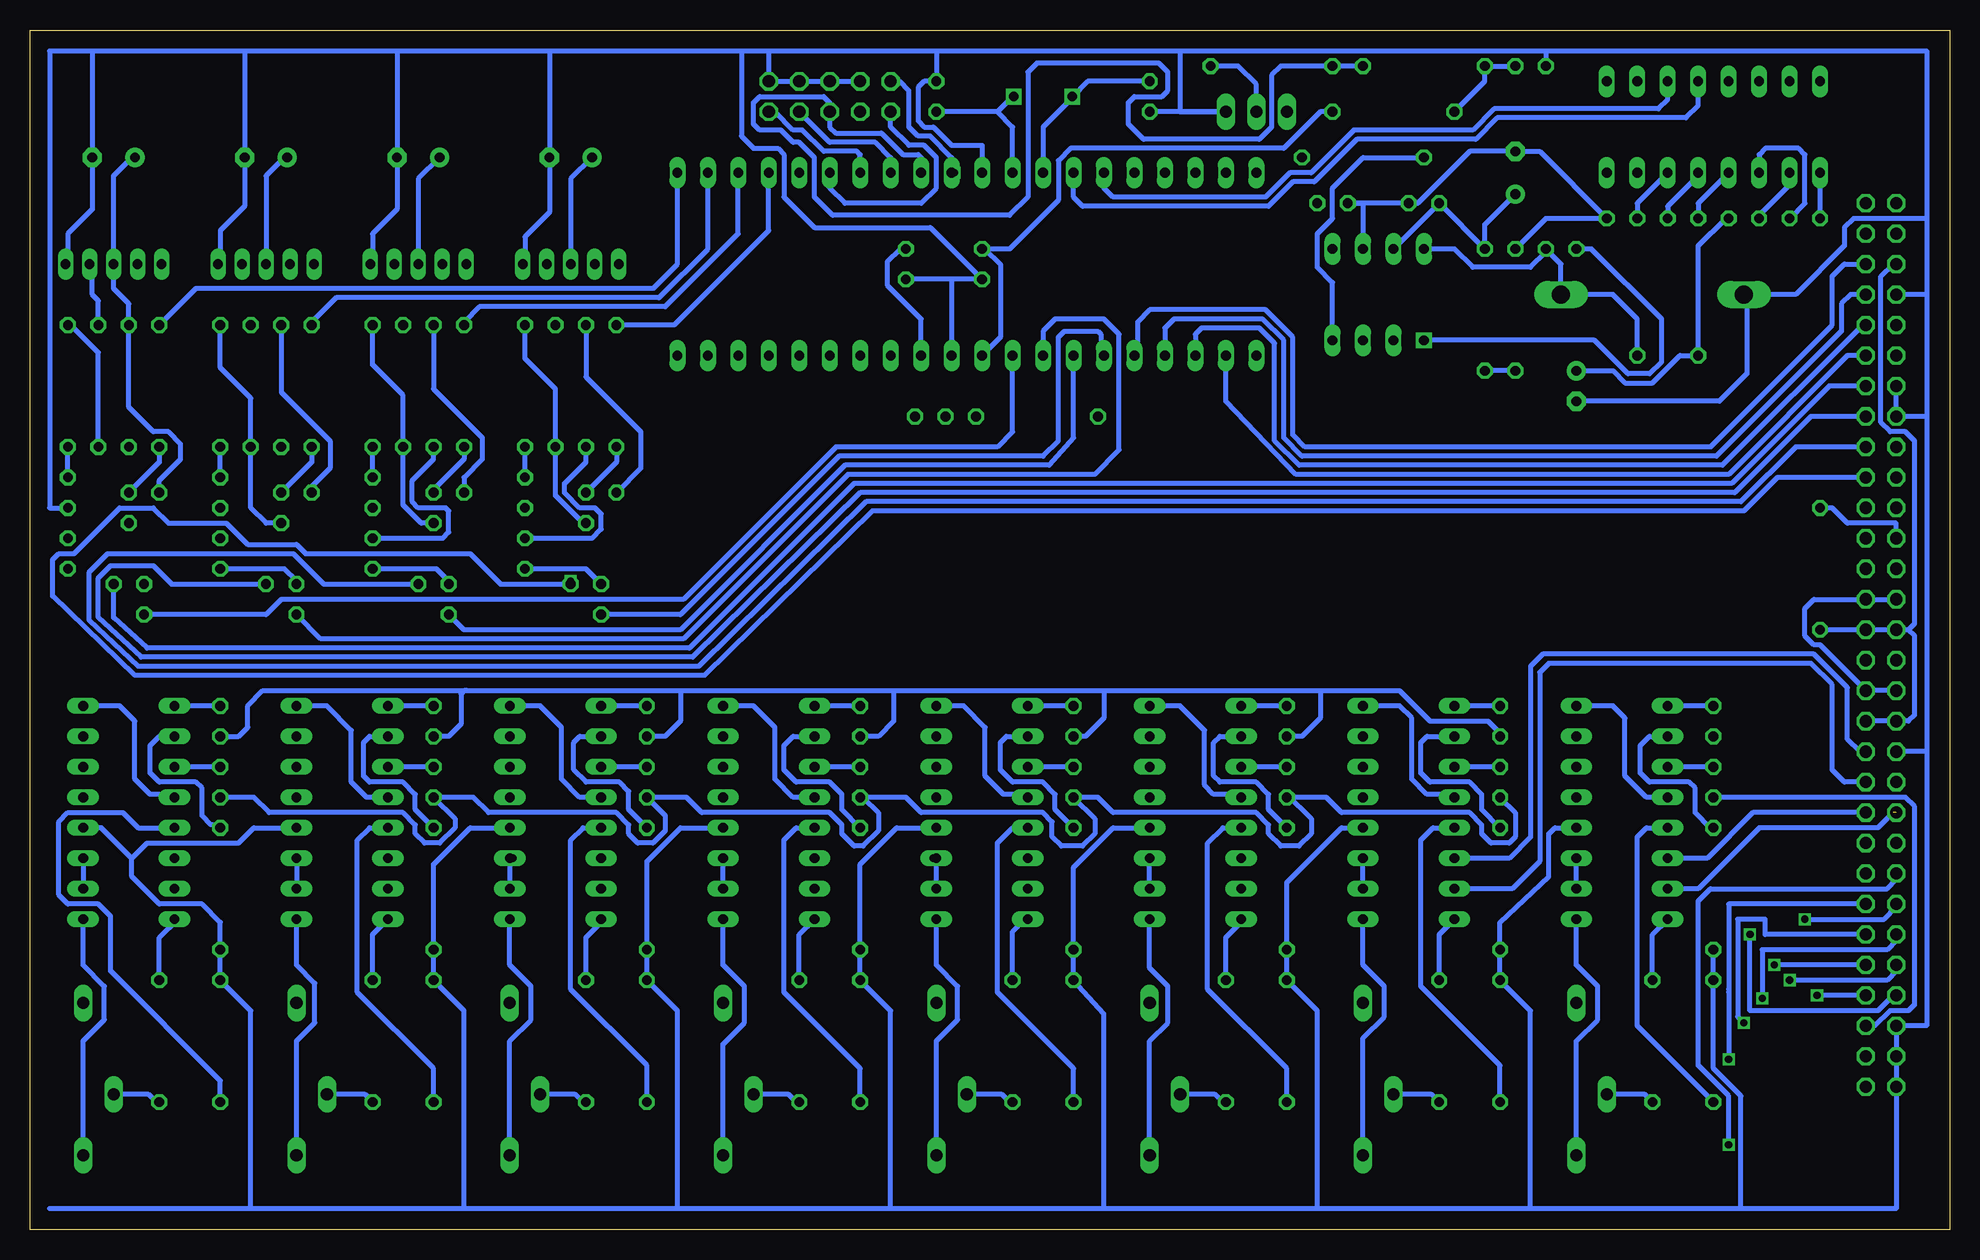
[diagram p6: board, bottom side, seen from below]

Size 160 x 100 mm. Coordinates in mm from the lower left corner, seen from the top.
Outline: 0,0 160,0 160,100 0,100 0,0
Copper layers (1*16): Top 0.035mm / dielectric 1.5mm / Bottom 0.035mm
Design rules "default": minimum track width 10mil, minimum drill 24mil, track to track 8mil, track to pad 8mil, pad to pad 8mil, via to via 8mil, smd to smd 8mil, copper to edge 40mil, drill to drill 8mil, minimum pad ring 10mil, minimum via ring 8mil, stop-mask expansion 4mil, vias tented up to drill 0mil, thermal gap 10mil

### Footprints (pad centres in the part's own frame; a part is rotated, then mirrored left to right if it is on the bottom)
C025-024X044 = drill 0.813 octagon: 1 -1.27,0; 2 1.27,0
E3,5-10 = drill 0.813 pad 1.6 round: + -1.778,0 | drill 0.813 pad 1.6 octagon: - 1.778,0
E2,5-5 = drill 0.813 pad 1.6 round: + -1.27,0 | drill 0.813 pad 1.6 octagon: - 1.27,0
C4111-15 = drill 1.499 long: A 7.62,0; C -7.62,0
DIL-8 = drill 0.813 square: P$1 -3.81,3.81 | drill 0.813 long: P$2 -3.81,1.27; P$3 -3.81,-1.27; P$4 -3.81,-3.81; P$5 3.81,-3.81; P$6 3.81,-1.27; P$7 3.81,1.27; P$8 3.81,3.81
0207/5V = drill 0.813 octagon: 1 -2.54,0; 2 2.54,0
LED3MM = drill 0.813 octagon: A -1.27,0; K 1.27,0
DIL40 = drill 0.813 long: 1 -24.13,-7.62; 2 -21.59,-7.62; 3 -19.05,-7.62; 4 -16.51,-7.62; 5 -13.97,-7.62; 6 -11.43,-7.62; 7 -8.89,-7.62; 8 -6.35,-7.62; 9 -3.81,-7.62; 10 -1.27,-7.62; 11 1.27,-7.62; 12 3.81,-7.62; 13 6.35,-7.62; 14 8.89,-7.62; 15 11.43,-7.62; 16 13.97,-7.62; 17 16.51,-7.62; 18 19.05,-7.62; 19 21.59,-7.62; 20 24.13,-7.62; 21 24.13,7.62; 22 21.59,7.62; 23 19.05,7.62; 24 16.51,7.62; 25 13.97,7.62; 26 11.43,7.62; 27 8.89,7.62; 28 6.35,7.62; 29 3.81,7.62; 30 1.27,7.62; 31 -1.27,7.62; 32 -3.81,7.62; 33 -6.35,7.62; 34 -8.89,7.62; 35 -11.43,7.62; 36 -13.97,7.62; 37 -16.51,7.62; 38 -19.05,7.62; 39 -21.59,7.62; 40 -24.13,7.62
0207/10 = drill 0.813 octagon: 1 -5.08,0; 2 5.08,0
0309/10 = drill 0.813 octagon: 1 -5.08,0; 2 5.08,0
SP19L = drill 1.016 long: A 5.715,-1.27; E -6.985,-1.27; S -1.905,1.27
MA10-2W = drill 1.016 octagon: 1 -11.43,-1.27; 2 -11.43,1.27; 3 -8.89,-1.27; 4 -8.89,1.27; 5 -6.35,-1.27; 6 -6.35,1.27; 7 -3.81,-1.27; 8 -3.81,1.27; 9 -1.27,-1.27; 10 -1.27,1.27; 11 1.27,-1.27; 12 1.27,1.27; 13 3.81,-1.27; 14 3.81,1.27; 15 6.35,-1.27; 16 6.35,1.27; 17 8.89,-1.27; 18 8.89,1.27; 19 11.43,-1.27; 20 11.43,1.27
MA05-2 = drill 1.016 octagon: 1 -5.08,-1.27; 2 -5.08,1.27; 3 -2.54,-1.27; 4 -2.54,1.27; 5 0,-1.27; 6 0,1.27; 7 2.54,-1.27; 8 2.54,1.27; 9 5.08,-1.27; 10 5.08,1.27
MA03-1 = drill 1.016 long: 1 -2.54,0; 2 0,0; 3 2.54,0
TO18 = drill 0.813 octagon: 1 -1.27,-1.27; 2 1.27,-1.27; 3 1.27,1.27
DIL-16 = drill 0.813 long: P$1 -3.81,8.89; P$2 -3.81,6.35; P$3 -3.81,3.81; P$4 -3.81,1.27; P$5 -3.81,-1.27; P$6 -3.81,-3.81; P$7 -3.81,-6.35; P$8 -3.81,-8.89; P$9 3.81,-8.89; P$10 3.81,-6.35; P$11 3.81,-3.81; P$12 3.81,-1.27; P$13 3.81,1.27; P$14 3.81,3.81; P$15 3.81,6.35; P$16 3.81,8.89
QUARZ16MHZ = drill 0.813 square: P$1 -2.44,0; P$2 2.44,0
TO-GEHÄUSE = drill 0.8 long: P$1 -4,0; P$2 -2,0; P$3 0,0; P$4 2,0; P$5 4,0

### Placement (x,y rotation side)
C1  43.81,85.56 0 top
C2  36.19,88.1 90 top
C3  31.11,70.32 270 top
C4  32.38,81.75 180 top
C5  34.92,96.99 180 top
C6  17.14,84.29 180 top
C7  27.3,84.29 180 top
C8  12.06,84.29 0 top
C9  22.22,84.29 180 top
C10  84.45,94.45 90 top
C11  66.67,94.45 90 top
C12  80.64,80.48 270 top
C13  86.99,80.48 270 top
C14  37.46,37.3 270 top
C15  37.46,42.38 270 top
C16  144.14,37.3 270 top
C17  144.14,42.38 270 top
C18  126.36,37.3 270 top
C19  126.36,42.38 270 top
C20  108.58,37.3 270 top
C21  108.58,42.38 270 top
C22  90.8,37.3 270 top
C23  90.8,42.38 270 top
C24  73.02,37.3 270 top
C25  73.02,42.38 270 top
C26  55.24,37.3 270 top
C27  55.24,42.38 270 top
C28  19.68,37.3 270 top
C29  19.68,42.38 270 top
C30  114.93,89.37 0 top
C31  127.63,89.37 0 top
C32  140.33,89.37 0 top
C33  153.03,89.37 0 top
D1  24.76,77.94 180 top
IC1  47.62,77.94 90 top
L1  23.49,72.86 180 top
LED1  51.43,85.56 180 top
LED2  118.74,61.43 270 top
LED3  118.74,56.35 270 top
LED4  131.44,61.43 270 top
LED5  131.44,56.35 270 top
LED6  144.14,61.43 270 top
LED7  144.14,56.35 270 top
LED8  156.84,61.43 270 top
LED9  156.84,56.35 270 top
LED10  84.96,67.78 180 top
MEGA16  81.91,80.48 180 top
R1  38.73,76.67 90 top
R2  36.19,76.67 270 top
R3  48.89,89.37 0 top
R4  46.35,93.18 180 top
R5  43.81,96.99 0 top
R6  56.51,96.99 180 top
R7  10.79,55.08 90 top
R8  37.46,15.71 90 top
R9  116.2,70.32 90 top
R10  118.74,70.32 90 top
R11  37.46,28.41 270 top
R12  144.14,15.71 90 top
R13  111.12,70.32 90 top
R14  128.9,70.32 90 top
R15  144.14,28.41 270 top
R16  126.36,15.71 90 top
R17  131.44,70.32 90 top
R18  123.82,70.32 90 top
R19  126.36,28.41 270 top
R20  108.58,15.71 90 top
R21  126.36,70.32 90 top
R22  141.6,70.32 90 top
R23  108.58,28.41 270 top
R24  90.8,15.71 90 top
R25  144.14,70.32 90 top
R26  136.52,70.32 90 top
R27  90.8,28.41 270 top
R28  73.02,15.71 90 top
R29  139.06,70.32 90 top
R30  154.3,70.32 90 top
R31  73.02,28.41 270 top
R32  55.24,15.71 90 top
R33  113.66,70.32 90 top
R34  156.84,70.32 90 top
R35  55.24,28.41 270 top
R36  19.68,15.71 90 top
R37  149.22,70.32 90 top
R38  151.76,70.32 90 top
R39  19.68,28.41 270 top
R40  76.07,67.78 0 top
RAN1.1  29.84,13.17 90 top
RAN1.2  24.76,15.71 90 top
RAN2.1  154.3,13.17 90 top
RAN2.2  149.22,15.71 90 top
RAN3.1  136.52,13.17 90 top
RAN3.2  131.44,15.71 90 top
RAN4.1  118.74,13.17 90 top
RAN4.2  113.66,15.71 90 top
RAN5.1  100.96,13.17 90 top
RAN5.2  95.88,15.71 90 top
RAN6.1  83.18,13.17 90 top
RAN6.2  78.1,15.71 90 top
RAN7.1  65.4,13.17 90 top
RAN7.2  60.32,15.71 90 top
RM1  47.62,13.17 90 top
RM2  42.54,15.71 90 top
SV1  5.71,48.73 90 top
SV2  5.71,74.13 90 top
SV3  5.71,23.33 90 top
SV4  93.34,94.45 0 top
SV5  57.78,93.18 180 top
T1  112.39,60.16 90 top
T2  125.09,60.16 90 top
T3  126.36,52.54 180 top
T4  137.79,60.16 90 top
T5  113.66,52.54 180 top
T6  139.06,52.54 180 top
T7  150.49,60.16 90 top
T8  151.76,52.54 180 top
U$1  19.68,91.91 90 top
U$2  75.56,94.45 0 top
U$3  45.08,34.76 0 top
U$4  151.76,34.76 0 top
U$5  133.98,34.76 0 top
U$6  116.2,34.76 0 top
U$7  98.42,34.76 0 top
U$8  80.64,34.76 0 top
U$9  62.86,34.76 0 top
U$10  27.3,34.76 0 top
U$11  114.93,80.48 180 top
U$12  127.63,80.48 180 top
U$13  140.33,80.48 180 top
U$14  153.03,80.48 180 top

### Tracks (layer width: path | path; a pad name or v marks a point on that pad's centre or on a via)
+5V  (via drill 0.6)
  Top 0.406: R3.1 43.56,89.37 41.27,91.66 R4.2 | v82.93,88.1 82.93,77.94 81.15,76.16 51.94,76.16 51.43,75.65 | SV3.1 6.98,12.15 8,12.15 8.5,12.66 8.5,15.2 8,15.71 3.42,15.71 1.9,17.23 1.9,44.92 3.17,46.19 18.16,46.19 29.33,57.62 29.33,71.08 29.84,71.59 C3.+ 33.9,71.59 38.48,76.16 50.92,76.16 51.43,75.65 | 51.43,74.38 IC1.P$4 51.43,75.65
  Bottom 0.406: SV4.2 87.5,95.72 86.74,94.96 86.74,91.91 85.97,91.15 84.96,91.15 83.18,89.37 83.18,88.35 v82.93,88.1 MEGA16.10 | C5.1 R5.1 38.73,95.72 R4.2 | C6.1 18.66,84.29 20.95,82 L1.2 22.47,72.86 24.76,70.57 27.05,70.57 28.06,71.59 C3.+ | R3.1 48.89,89.37 51.43,86.83 51.43,84.29 52.7,83.02 52.7,80.23 51.43,78.96 IC1.P$4
+12V
  Top 0.406: C33.+ 145.16,89.37 143.38,91.15 140.08,91.15 138.55,89.62 C32.+ 132.96,89.37 130.93,91.4 127.88,91.4 C31.+ 119.5,89.37 117.47,91.4 114.93,91.4 112.9,89.37 C30.+ 112.14,90.39 82.67,90.39 81.91,89.62 81.91,86.58 81.4,86.07 67.18,86.07 66.67,86.58 66.67,89.62 66.16,90.13 60.07,90.13 59.05,89.12 59.05,86.07 57.02,84.04 47.87,84.04 46.35,82.51 IC1.P$7 | U$11.P$3 114.93,76.67 R33.2 | U$12.P$3 127.63,76.67 R21.2 | U$13.P$3 140.33,76.67 R29.2 | T7.3 149.22,59.91 152.78,56.35 158.36,56.35 158.36,42.38 | SV3.3 5.71,13.17 5.71,3.01 6.98,1.74 158.36,1.74 158.36,42.38 | C29.2 20.19,41.11 21.46,39.84 35.94,39.84 37.21,41.11 C15.2 | C17.2 145.41,41.11 146.68,42.38 158.36,42.38
  Bottom 0.406: IC1.P$7 C1.1 R1.2 38.73,83.78 C2.+ | C33.+ 151.51,89.37 153.03,87.85 U$14.P$3 153.03,78.45 151.76,77.18 R38.2 152.01,75.15 151.76,74.89 151.76,68.54 149.73,66.51 148.46,66.51 147.44,65.49 147.44,64.22 149.22,62.45 T7.3 | C32.+ 138.55,89.62 140.33,87.85 U$13.P$3 | U$12.P$3 127.63,87.59 C31.+ | U$11.P$3 114.93,87.59 C30.+ | T2.3 123.82,62.7 122.3,64.22 122.3,66 126.36,70.07 R21.2 | T1.3 109.09,63.46 109.09,66.51 113.66,71.08 R33.2 | T4.3 136.52,61.94 135,63.46 135,65.75 139.06,69.81 R29.2 139.06,75.65 | 52.45,44.92 45.84,44.92 43.3,42.38 38.48,42.38 37.21,41.11 C15.2 | 70.48,44.92 52.45,44.92 | 88.01,44.92 70.48,44.92 | 105.79,44.92 88.01,44.92 | 123.57,44.92 105.79,44.92 | C27.2 53.97,41.11 52.45,42.63 52.45,44.92 | C25.2 72,41.11 70.48,42.63 70.48,44.92 | C23.2 89.28,41.11 88.01,42.38 88.01,44.92 | C21.2 107.06,41.11 105.79,42.38 105.79,44.92 | C19.2 125.09,41.11 124.07,42.13 124.07,44.67 123.82,44.92 123.57,44.92 | 123.57,44.92 140.58,44.92 141.85,43.65 141.85,41.87 142.62,41.11 C17.2
-12V
  Top 0.406: C28.2 19.93,36.03 21.2,34.76 36.19,34.76 C14.2
  Bottom 0.406: C16.2 141.35,36.03 140.08,34.76 128.9,34.76 127.88,33.74 127.88,32.98 127.12,32.22 125.85,32.22 124.58,33.49 124.58,34.25 C18.2 123.06,36.03 121.79,34.76 111.12,34.76 110.1,33.74 110.1,32.98 109.34,32.22 108.07,32.22 107.06,33.24 107.06,34.51 C20.2 105.28,36.03 104.01,34.76 93.34,34.76 92.32,33.74 92.32,32.98 91.31,31.97 90.55,31.97 89.28,33.24 89.28,34.76 90.55,36.03 C22.2 86.99,36.03 85.72,34.76 75.56,34.76 74.8,34 74.8,32.73 74.04,31.97 72.26,31.97 71.24,32.98 71.24,34.25 C24.2 70.99,36.03 69.72,34.76 57.78,34.76 56.76,33.74 56.76,32.98 55.75,31.97 54.22,31.97 53.21,32.98 53.21,34.25 55.24,36.28 C26.2 51.94,36.03 50.67,34.76 40,34.76 38.98,33.74 38.98,32.98 38.22,32.22 36.7,32.22 36.19,32.73 36.19,34.76 C14.2 | SV3.5 6.22,16.98 4.95,18.25 3.42,18.25 2.92,18.76 2.92,35.27 3.68,36.03 C28.2
AMP1
  Bottom 0.406: U$10.P$16 28.06,43.65 27.05,42.63 27.05,37.81 25.27,36.03 U$10.P$4
AN1+
  Bottom 0.406: SV3.19 16.38,34.76 20.19,30.95 U$10.P$6
AN1-  (1 unrouted)
  Bottom 0.406: 4.69,34.76 5.96,33.49 15.87,33.49 20.95,28.41 U$10.P$7
AN2+
  Top 0.406: U$4.P$6 146.17,30.95 142.62,27.39 142.62,4.28 141.6,3.26 11.04,3.26 10.03,4.28 10.03,17.23 8.25,19.01 8.25,20.79 6.22,20.79 5.71,21.3 5.71,31.2 6.73,32.22 SV3.17
AN2-
  Top 0.406: U$4.P$7 147.19,28.41 145.92,27.14 145.92,3.52 144.9,2.5 10.54,2.5 9.27,3.77 9.27,16.73 7.74,18.25 3.42,18.25 2.92,18.76 2.92,31.71 3.42,32.22 SV3.18
AN3+
  Top 0.406: U$5.P$6 127.38,30.95 125.09,28.66 125.09,9.87 123.57,8.34 18.66,8.34 17.14,9.87 12.57,9.87 10.79,11.65 10.79,17.74 9.01,19.52 9.01,29.17 8.5,29.68 SV3.15
AN3-  (via drill 0.6)
  Top 0.406: U$5.P$7 128.9,28.41 127.88,27.39 127.88,5.04 126.87,4.03 21.46,4.03 v18.41,7.07
  Bottom 0.406: SV3.16 4.44,29.17 5.2,28.41 19.93,28.41 20.95,27.39 20.95,13.68 18.41,11.14 v18.41,7.07
AN4+  (via drill 0.6)
  Top 0.406: U$6.P$6 109.34,30.95 107.31,28.92 107.31,15.71 105.02,13.42 19.17,13.42 v18.41,14.19
  Bottom 0.406: SV3.13 18.41,27.14 18.41,20.03 | 18.41,20.03 18.41,19.77 | 18.41,20.03 v18.41,14.19
AN4-  (via drill 0.6)
  Top 0.406: U$6.P$7 110.87,28.41 110.1,27.65 110.1,10.12 109.09,9.11 18.92,9.11 17.39,10.63 13.08,10.63 12.06,11.65 v12.06,25.87
  Bottom 0.406: SV3.14 4.44,26.89 5.46,25.87 v12.06,25.87 11.81,25.87
AN5+  (via drill 0.6)
  Top 0.406: U$7.P$6 91.05,30.95 89.53,29.43 89.53,16.22 88.26,14.95 21.46,14.95 19.17,17.23 v17.14,17.23
  Bottom 0.406: SV3.11 15.36,24.6 15.36,25.87 17.65,25.87 17.65,17.74 v17.14,17.23
AN5-  (via drill 0.6)
  Top 0.406: U$7.P$7 93.09,28.41 92.07,27.39 92.07,15.2 91.05,14.19 21.2,14.19 19.17,16.22 15.62,16.22 v15.62,19.27
  Bottom 0.406: SV3.12 4.44,24.09 5.2,23.33 15.62,23.33 v15.62,19.27
AN6+  (via drill 0.6)
  Top 0.406: U$8.P$6 73.53,30.95 71.24,28.66 71.24,18 69.72,16.47 22.22,16.47 16.63,22.06 v14.6,22.06
  Bottom 0.406: SV3.9 v14.6,22.06
AN6-  (via drill 0.6)
  Top 0.406: U$8.P$7 75.56,28.41 74.29,27.14 74.29,16.73 73.27,15.71 21.71,15.71 19.17,18.5 16.89,20.79 v13.33,20.79
  Bottom 0.406: SV3.10 4.44,21.55 5.2,20.79 v13.33,20.79
AN7+  (via drill 0.6)
  Top 0.406: U$9.P$6 57.53,30.95 51.18,24.6 21.2,24.6 18.66,27.14 11.04,27.14 v11.04,19.52
  Bottom 0.406: SV3.7 v11.04,19.52
AN7-  (via drill 0.6)
  Top 0.406: U$9.P$7 57.78,28.41 51.43,22.06 22.73,22.06 20.19,24.6 v16.63,24.6
  Bottom 0.406: SV3.8 4.69,19.52 5.96,18.25 16.63,18.25 v16.63,24.6
DIG1IN
  Bottom 0.406: SV2.9 8.5,72.86 18.41,62.95 54.48,62.95 60.32,69.05 MEGA16.22
DIG2IN
  Bottom 0.406: SV2.11 7.23,75.4 18.92,63.72 54.22,63.72 56.26,65.75 56.26,73.88 57.53,75.15 62.35,75.15 62.86,74.64 MEGA16.23
DIG3IN
  Bottom 0.406: SV2.13 8.25,77.94 9.01,77.18 9.01,74.89 19.43,64.48 53.97,64.48 55.49,66 55.49,74.13 57.27,75.91 64.64,75.91 65.4,75.15 MEGA16.24
DIG4IN
  Bottom 0.406: SV2.15 8.76,80.48 9.77,79.46 9.77,75.4 19.93,65.24 53.72,65.24 54.73,66.26 54.73,74.38 57.02,76.67 66.67,76.67 67.69,75.65 67.69,73.37 67.94,73.11 MEGA16.25
FUSE_GND
  Top 0.406: LED2.K 119.5,60.16 120.26,60.92 120.26,76.16 118.74,77.69 118.74,79.97 118.99,80.23 118.93,80.29 U$11.P$1 | LED4.K 132.2,60.16 133.22,61.18 133.22,76.16 131.69,77.69 131.69,80.23 131.63,80.29 U$12.P$1 | LED6.K 145.16,60.16 145.92,60.92 145.92,76.92 144.39,78.45 144.39,80.48 U$13.P$1 | SV2.6 4.69,67.78 4.44,67.53 SV2.4 SV2.2 SV1.20 SV1.18 4.44,57.37 | C5.2 33.65,92.42 C2.- | MEGA16.31 83.18,71.08 81.4,69.3 79.12,69.3 77.59,67.78 R40.1
  Bottom 0.406: SV3.6 SV3.4 SV3.2 | SV3.6 4.44,1.74 17.39,1.74 | 141.6,1.74 158.36,1.74 | 123.82,1.74 141.6,1.74 | 106.04,1.74 123.82,1.74 | 88.26,1.74 106.04,1.74 | 70.48,1.74 88.26,1.74 | 52.7,1.74 70.48,1.74 | 34.92,1.74 52.7,1.74 | 17.39,1.74 34.92,1.74 | 154.81,98.26 158.36,98.26 158.36,60.16 LED8.K | 154.81,98.26 142.11,98.26 | 142.11,98.26 129.41,98.26 | 129.41,98.26 116.71,98.26 | 116.71,98.26 100.71,98.26 | 100.71,98.26 98.42,98.26 | 98.42,98.26 84.45,98.26 | 84.45,98.26 64.13,98.26 | 64.13,98.26 33.65,98.26 | 33.65,98.26 1.9,98.26 1.9,84.29 | 1.9,84.29 1.9,77.94 | 1.9,67.78 1.9,39.84 | 1.9,67.78 SV2.6 4.69,67.78 4.44,68.03 SV2.8 | 17.39,1.74 17.39,11.14 19.68,13.42 R36.2 R39.2 | 34.92,1.74 34.92,18.25 R8.2 R11.2 37.46,25.62 33.4,29.43 33.4,32.98 32.89,33.49 U$10.P$12 | 52.7,1.74 52.7,18.25 R32.2 R35.2 55.24,28.92 50.67,33.49 U$3.P$12 | 70.48,1.74 70.48,18 R28.2 R31.2 73.02,30.19 69.72,33.49 U$9.P$12 | 88.26,1.74 88.26,18.25 R24.2 R27.2 90.8,30.44 87.75,33.49 U$8.P$12 | 106.04,1.74 106.04,18.25 R20.2 R23.2 108.58,30.7 105.79,33.49 U$7.P$12 101.98,33.49 | 123.82,1.74 123.82,18.25 R16.2 R19.2 126.36,30.44 123.31,33.49 U$6.P$12 | 141.6,1.74 141.6,18.25 R12.2 R15.2 144.14,25.62 145.66,27.14 149.22,27.14 151.51,29.43 151.51,30.95 | 154.81,98.26 C33.- 154.81,85.05 156.84,83.02 156.84,80.73 157.09,80.48 U$14.P$1 | 142.11,98.26 C32.- 142.11,85.31 144.14,83.27 144.14,80.73 144.39,80.48 U$13.P$1 | 129.41,98.26 C31.- 129.41,85.05 131.44,83.02 131.44,80.99 131.69,80.73 131.63,80.67 U$12.P$1 | 116.71,98.26 C30.- 116.71,84.8 118.74,82.77 118.74,80.73 118.99,80.48 U$11.P$1 | 98.42,98.26 SV4.10 SV4.8 SV4.6 SV4.4
  Bottom 0.406: 84.45,98.26 C10.2 85.47,95.72 85.97,95.21 85.97,92.42 85.47,91.91 84.7,91.91 83.18,90.39 80.64,90.39 MEGA16.11 | C11.1 SV5.1 64.13,93.18 64.13,98.26 | 33.65,98.26 C5.2 | IC1.P$6 48.89,85.56 LED1.K C1.2 44.32,85.56 40,89.88 C2.- 34.16,89.88 C7.1 33.65,84.29 R2.1 | 1.9,77.94 SV2.14 | 1.9,77.94 1.9,67.78 | 1.9,84.29 8,84.29 8.76,83.53 8.76,82 12.82,77.94 D1.A 17.14,77.69 16.89,77.43 16.89,71.34 19.17,69.05 C3.- | 87.24,79.21 C13.2 83.18,79.21 | 83.18,79.21 C12.2 84.96,83.53 94.61,83.53 97.15,86.07 97.15,89.62 97.66,90.13 99.69,90.13 100.71,91.15 100.71,98.26 | 83.18,79.21 MEGA16.31 | U$4.P$12 154.05,33.49 151.51,30.95 | U$5.P$12 141.35,33.49 142.62,32.22 150.24,32.22 151.51,30.95 | R7.2 9.77,60.16 8.5,58.89 4.44,58.89 SV1.18 4.44,57.37 | 1.9,39.84 SV1.4 | 1.9,39.84 1.9,16.98 SV3.6
FUSE_TEST1
  Bottom 0.406: T5.3 105.79,51.27 92.58,64.48 75.56,64.48 74.29,65.75 74.29,74.38 73.78,74.89 70.99,74.89 70.73,74.64 70.73,73.11 MEGA16.26
FUSE_TEST2
  Bottom 0.406: T3.3 123.82,50 105.79,50 92.07,63.72 75.05,63.72 73.02,66 MEGA16.27
FUSE_TEST3
  Bottom 0.406: MEGA16.28 75.56,74.89 74.54,75.91 70.48,75.91 69.21,74.64 69.21,64.99 71.24,62.95 91.82,62.95 105.53,49.24 135.76,49.24 T6.3
FUSE_TEST4
  Bottom 0.406: T8.3 140.33,51.27 139.06,52.54 105.53,52.54 92.83,65.24 79.37,65.24 78.1,66.51 MEGA16.29
IGN1
  Bottom 0.406: R13.2 106.29,75.4 98.42,83.27 MEGA16.4
IGN1OUT  (via drill 0.6)
  Top 0.406: v114.93,54.06 114.93,71.34 112.39,73.88 112.39,76.42 110.87,77.94 110.87,80.48 U$11.P$5
  Bottom 0.406: SV2.1 14.35,62.7 17.14,59.91 89.78,59.91 103.75,46.19 151.25,46.19 158.11,52.79 158.11,55.84 157.6,56.35 156.33,56.35 152.52,60.16 149.73,60.16 148.46,58.89 143.63,58.89 141.85,57.11 137.79,57.11 137.03,56.35 123.31,56.35 120.77,53.81 115.18,53.81 v114.93,54.06 T5.1
IGN2
  Bottom 0.406: MEGA16.3 100.96,83.02 107.06,76.92 122.55,76.92 123.82,75.65 R18.2
IGN2OUT
  Top 0.406: T3.1 127.63,71.59 125.09,74.13 125.09,76.42 123.57,77.94 123.57,80.23 123.63,80.29 U$12.P$5
  Bottom 0.406: SV2.3 12.82,65.24 17.39,60.67 90.29,60.67 104.26,46.95 151,46.95 155.06,50.76 155.06,54.83 153.54,56.35 138.04,56.35 135.5,53.81 T3.1
IGN3
  Bottom 0.406: MEGA16.2 103.5,81.75 107.56,77.69 134.49,77.69 136.52,75.65 R26.2
IGN3OUT
  Top 0.406: T6.1 140.33,61.94 137.79,64.48 137.79,77.43 136.52,78.7 136.52,80.23 136.33,80.42 U$13.P$5
  Bottom 0.406: SV2.5 11.55,67.78 17.9,61.43 90.8,61.43 104.77,47.71 150.74,47.71 154.3,51.02 154.3,54.32 153.28,55.33 149.73,55.33 148.2,53.81 T6.1
IGN4
  Bottom 0.406: MEGA16.1 106.04,80.48 108.07,78.45 146.17,78.45 R37.2
IGN4OUT
  Top 0.406: T8.1 153.03,54.83 147.7,60.16 147.7,77.18 148.97,78.45 148.97,80.48 U$14.P$5 149.03,80.42
  Bottom 0.406: SV2.7 10.03,70.32 18.16,62.19 91.31,62.19 105.02,48.48 150.24,48.48 153.03,51.02 T8.1
N$1
  Bottom 0.406: R2.2 R1.1
N$2
  Bottom 0.406: C4.2 29.84,81.75 24,75.91 24,72.35 25.01,71.34 26.79,71.34 29.59,74.13 IC1.P$1
N$3
  Bottom 0.406: IC1.P$8 41.27,81.75 39.75,80.23 34.92,80.23 33.65,81.5 C4.1 32.38,80.48 D1.C 28.06,77.94 26.03,75.91 L1.1
N$4
  Bottom 0.406: C6.2 15.87,84.54 13.33,87.08 U$1.P$2
N$5
  Top 0.406: R3.2 53.97,86.83 LED1.A
N$6
  Bottom 0.406: C7.2 26.03,85.56 U$1.P$6
N$7
  Bottom 0.406: U$1.P$5 20.7,88.1 23.49,85.31 C9.1
N$8
  Bottom 0.406: U$1.P$1 10.54,88.1 10.79,87.85 C8.1
N$9
  Bottom 0.406: C8.2 12.06,85.56 12.06,89.62 12.57,90.13 15.36,90.13 15.87,89.62 15.87,88.35 16.12,88.1 U$1.P$3
N$10
  Bottom 0.406: C9.2 20.95,85.56 U$1.P$4
N$11
  Top 0.406: SV1.17 11.3,57.62 12.06,58.38 12.06,90.13 13.33,91.4 16.38,91.4 18.41,93.43 U$1.P$13
N$12
  Top 0.406: SV1.19 7.49,60.16 8.5,61.18 8.5,90.39 11.04,92.93 14.85,92.93 15.87,93.94 U$1.P$14
N$13
  Bottom 0.406: MEGA16.14 73.02,86.07 72.26,85.31 56.76,85.31 54.73,87.34 52.95,87.34 49.4,90.89 39.49,90.89 37.71,92.67 21.97,92.67 20.95,93.69 U$1.P$12
N$14
  Bottom 0.406: MEGA16.15 70.48,86.83 69.72,86.07 57.02,86.07 54.99,88.1 53.21,88.1 49.65,91.66 39.75,91.66 37.97,93.43 24.25,93.43 23.49,94.2 U$1.P$11
N$15
  Bottom 0.406: MEGA16.13 75.56,91.91 73.02,94.45 U$2.P$1 71.85,95.72 C11.2
N$16
  Bottom 0.406: U$2.P$2 78.1,94.45 79.37,93.18 | 79.37,93.18 C10.1 | MEGA16.12 78.1,91.91 79.37,93.18
N$17
  Top 0.406: MEGA16.17 65.4,77.69 64.64,76.92 37.97,76.92 34.41,73.37 30.6,73.37 28.57,71.34 28.57,57.87 18.16,47.46 SV1.9
N$18
  Bottom 0.406: MEGA16.30 79.12,74.38 79.12,80.48 80.39,81.75 C12.1 78.35,81.75 74.29,85.81 74.29,89.12 73.27,90.13 55.49,90.13 52.45,93.18 R4.1
N$19
  Bottom 0.406: C13.1 87.5,81.75 88.51,80.73 88.51,78.7 85.72,75.91 MEGA16.32
N$20
  Bottom 0.406: MEGA16.9 85.72,89.37 85.97,89.62 87.24,89.62 89.02,91.4 92.83,91.4 93.34,91.91 SV4.5 93.34,93.94 93.85,94.45 99.18,94.45 99.69,93.94 99.69,92.16 99.18,91.66 97.4,91.66 96.39,90.64 95.88,90.64 94.61,89.37 94.61,86.07 93.09,84.54 78.35,84.54 76.83,86.07 76.83,96.48 76.07,97.24 65.91,97.24 65.15,96.48 65.15,94.96 65.65,94.45 67.94,94.45 68.45,93.94 68.45,92.16 67.18,90.89 57.53,90.89 56.51,91.91 56.51,96.23 55.75,96.99 R6.2 R5.2
N$21
  Top 0.406: SV2.20 4.44,96.48 6.22,98.26 66.92,98.26 67.94,97.24 MEGA16.16 67.94,87.85
N$22
  Bottom 0.406: R6.1 59.3,96.99 57.78,95.47 SV5.2
N$23
  Top 0.406: MEGA16.20 57.53,88.1 54.48,91.15 48.38,91.15 45.08,87.85 32.38,87.85 27.55,92.67 20.95,92.67 19.68,93.94 19.68,96.74 18.92,97.5 17.9,97.5 17.14,96.74 17.14,93.69 15.62,92.16 11.55,92.16 9.52,90.13 9.52,59.91 8.5,58.89 6.22,58.89 5.71,58.38 5.71,56.86 5.2,56.35 4.69,56.35 4.44,56.1 SV1.16
N$24
  Top 0.406: MEGA16.19 60.32,79.72 59.05,78.45 36.95,78.45 33.4,74.89 30.09,74.89 27.05,71.84 27.05,59.14 24.25,56.35 6.47,56.35 5.71,55.59 5.71,48.73 SV1.10
N$25
  Bottom 0.406: SV1.5 SV1.6 3.42,42.38 2.92,42.89 2.92,49.49 3.42,50 | R7.1 SV1.11 SV1.12 3.42,50 | 3.42,50 2.92,50.51 2.92,65.75 3.68,66.51 4.95,66.51 5.71,67.27 5.71,79.46 4.69,80.48 SV2.16
N$26
  Top 0.406: MEGA16.18 62.86,78.45 62.1,77.69 37.46,77.69 33.9,74.13 30.35,74.13 27.81,71.59 27.81,58.38 24.51,55.08 SV1.15
N$27
  Bottom 0.406: C14.1 U$3.P$3
N$28
  Bottom 0.406: U$3.P$1 41.27,43.4 41.02,43.65 C15.1
N$29
  Top 0.406: U$3.P$11 50.67,30.95 51.94,32.22 51.94,63.46 53.21,64.73 90.04,64.73 90.8,65.75 MEGA16.34
  Bottom 0.406: U$3.P$10 U$3.P$11
N$30
  Bottom 0.406: RM2.2 42.54,24.6 U$3.P$8
N$31
  Bottom 0.406: RM1.E 48.89,15.96 47.11,17.74 47.11,20.28 48.89,22.06 U$3.P$9
N$32
  Bottom 0.406: RM1.S 43.18,11.27 RM2.1
N$33
  Top 0.406: SV1.2 5.71,38.57 17.14,38.57 18.41,37.3 39.75,37.3 41.02,36.03 U$3.P$4
  Bottom 0.406: U$3.P$16 45.84,43.65 44.83,42.63 44.83,37.55 43.56,36.28 41.27,36.28 U$3.P$4
N$34
  Bottom 0.406: R11.1 38.98,35.01 38.98,36.28 40,37.3 43.3,37.3 44.06,38.06 44.06,40.6 43.56,41.11 U$3.P$2
N$35
  Bottom 0.406: C16.1 U$4.P$3
N$36
  Bottom 0.406: SV1.3 7.49,39.84 8.5,40.86 8.5,45.17 11.3,47.97 33.9,47.97 34.92,46.95 34.92,32.73 36.7,30.95 41.02,30.95 41.27,30.7 U$3.P$6
N$37
  Bottom 0.406: SV1.1 8.76,37.3 9.77,38.32 9.77,45.43 11.55,47.21 33.4,47.21 34.16,46.44 34.16,30.7 36.44,28.41 U$3.P$7
N$38
  Bottom 0.406: C17.1 U$4.P$1
N$39
  Top 0.406: U$4.P$11 153.54,30.95 153.54,36.79 153.03,37.3 142.87,37.3 141.6,38.57 141.6,45.43 137.03,50 111.88,50 106.04,55.84 MEGA16.40
  Bottom 0.406: U$4.P$11 U$4.P$10
N$40
  Bottom 0.406: U$4.P$8 147.7,25.87 149.22,24.35 RAN2.2.2
N$41
  Bottom 0.406: RAN2.1.E 155.57,15.71 153.79,17.49 153.79,20.28 155.57,22.06 155.57,25.36 155.82,25.62 U$4.P$9
N$42
  Bottom 0.406: RAN2.2.1 149.47,10.63 150.11,11.27 RAN2.1.S
N$43
  Bottom 0.406: U$4.P$2 149.22,41.11 149.98,40.35 149.98,38.06 149.22,37.3 146.17,37.3 145.66,36.79 145.66,34.51 144.9,33.74 144.39,33.74 R15.1
N$44
  Bottom 0.406: U$4.P$16 152.52,43.65 151.25,42.38 151.25,37.55 149.98,36.28 147.7,36.28 U$4.P$4
N$45
  Top 0.406: U$11.P$2 116.93,76.13 R9.2
N$47
  Bottom 0.406: 130.42,38.57 U$5.P$3 C18.1
N$48
  Bottom 0.406: C19.1 U$5.P$1
N$49
  Bottom 0.406: C26.1 U$9.P$3
N$50
  Bottom 0.406: RAN3.2.2 131.44,24.6 U$5.P$8
N$51
  Bottom 0.406: RAN3.1.E 137.79,15.71 136.27,17.23 136.27,20.54 137.79,22.06 U$5.P$9
N$52
  Bottom 0.406: RAN3.1.S 132.07,11.27 RAN3.2.1
N$53
  Bottom 0.406: R19.1 127.88,35.01 127.88,36.28 128.9,37.3 131.69,37.3 132.2,37.81 132.2,40.6 131.69,41.11 U$5.P$2
N$54
  Bottom 0.406: U$5.P$16 135.25,43.65 133.22,41.62 133.22,37.3 131.95,36.03 U$5.P$4 129.92,36.03
N$55
  Bottom 0.406: U$6.P$16 117.47,43.65 115.69,41.87 115.69,37.55 114.17,36.03 U$6.P$4
N$56
  Bottom 0.406: U$7.P$16 99.69,43.65 97.91,41.87 97.91,37.55 96.39,36.03 U$7.P$4
N$57
  Bottom 0.406: C20.1 U$6.P$3
N$58
  Bottom 0.406: C21.1 U$6.P$1
N$59
  Bottom 0.406: C27.1 U$9.P$1
N$60
  Bottom 0.406: U$6.P$8 112.39,25.62 113.66,24.35 RAN4.2.2
N$61
  Bottom 0.406: RAN4.1.E 120.01,15.71 118.23,17.49 118.23,20.28 120.01,22.06 U$6.P$9
N$62
  Bottom 0.406: RAN4.2.1 113.91,10.63 114.55,11.27 RAN4.1.S
N$63
  Bottom 0.406: U$6.P$2 114.17,41.11 114.68,40.6 114.68,38.32 113.66,37.3 110.87,37.3 110.1,36.54 110.1,35.01 R23.1
N$64
  Bottom 0.406: U$8.P$16 82.16,43.65 80.39,41.87 80.39,37.81 78.86,36.28 77.34,36.28 77.08,36.03 U$8.P$4
N$65
  Bottom 0.406: U$9.P$16 64.13,43.65 62.1,41.62 62.1,37.05 61.34,36.28 59.05,36.28 U$9.P$4
N$66
  Top 0.406: R14.2 128.9,75.65 129.63,76.38 U$12.P$2
N$67
  Bottom 0.406: C22.1 U$7.P$3
N$68
  Bottom 0.406: C23.1 U$7.P$1
N$69
  Bottom 0.406: C28.1 U$10.P$3
N$70
  Bottom 0.406: RAN5.2.2 95.88,24.6 U$7.P$8
N$71
  Bottom 0.406: RAN5.1.E 102.23,15.46 100.45,17.23 100.45,20.28 102.23,22.06 U$7.P$9
N$72
  Bottom 0.406: RAN5.2.1 96.13,10.63 96.77,11.27 RAN5.1.S
N$73
  Bottom 0.406: R27.1 92.32,35.01 92.32,36.28 93.34,37.3 96.13,37.3 97.15,38.32 97.15,40.35 96.39,41.11 U$7.P$2
N$74
  Bottom 0.406: T1.1 113.91,58.89 116.2,61.18 R9.1 116.2,70.07 118.74,72.61 R10.2
N$75
  Bottom 0.406: R13.1 111.12,63.97 T1.2
N$76
  Bottom 0.406: LED3.K 113.66,55.08 T5.2
N$77
  Bottom 0.406: C24.1 U$8.P$3
N$78
  Bottom 0.406: C25.1 U$8.P$1
N$79
  Bottom 0.406: 23.74,43.65 U$10.P$1 C29.1
N$80
  Bottom 0.406: U$8.P$8 76.83,26.12 78.1,24.85 RAN6.2.2
N$81
  Bottom 0.406: RAN6.1.E 84.45,15.71 82.67,17.49 82.67,20.28 84.45,22.06 U$8.P$9
N$82
  Bottom 0.406: RAN6.2.1 78.35,10.63 78.99,11.27 RAN6.1.S
N$83
  Bottom 0.406: R31.1 74.54,35.01 74.54,36.28 75.56,37.3 78.1,37.3 79.12,38.32 79.12,40.6 78.61,41.11 U$8.P$2
N$84
  Bottom 0.406: T2.1 127.38,58.89 128.9,60.41 R14.1 128.9,69.56 131.44,72.1 R17.2
N$85
  Bottom 0.406: T2.2 126.61,61.43 123.82,64.22 R18.1
N$86
  Bottom 0.406: LED4.A R17.1
N$87
  Bottom 0.406: U$9.P$8 59.05,25.62 60.32,24.35 RAN7.2.2
N$88
  Top 0.406: U$5.P$11 135.25,30.95 133.98,32.22 133.98,45.68 130.68,48.98 111.63,48.98 103.5,57.11 103.5,72.61 103.25,72.86 MEGA16.39
  Bottom 0.406: U$5.P$11 U$5.P$10
N$89  (via drill 0.6)
  Top 0.406: v119.76,30.95 117.72,30.95 116.2,32.47 116.2,44.92 112.9,48.22 110.87,48.22 100.96,58.13 MEGA16.38 100.71,73.11
  Bottom 0.406: U$6.P$11 v119.76,30.95 120.01,30.7 U$6.P$10
N$90
  Top 0.406: U$7.P$11 104.77,30.95 106.29,32.47 106.29,43.4 104.77,44.92 99.44,44.92 98.42,51.27 MEGA16.37
  Bottom 0.406: 102.23,28.16 U$7.P$10 U$7.P$11
N$91  (via drill 0.6)
  Top 0.406: v84.7,30.95 86.23,30.95 88.26,32.98 88.26,62.45 89.02,63.21 94.61,63.21 95.88,64.48 MEGA16.36
  Bottom 0.406: U$8.P$11 v84.7,30.95 84.45,30.7 U$8.P$10
N$92
  Top 0.406: U$9.P$11 68.45,30.95 69.72,32.22 69.72,62.45 71.24,63.97 92.32,63.97 93.34,65.24 MEGA16.35
  Bottom 0.406: U$9.P$10 66.42,28.41 66.67,28.66 U$9.P$11
N$93
  Bottom 0.406: RAN7.1.E 66.67,15.71 65.15,17.23 65.15,20.28 66.67,21.81 U$9.P$9
N$94
  Bottom 0.406: RAN7.2.1 60.57,10.63 61.21,11.27 RAN7.1.S
N$95
  Bottom 0.406: R35.1 56.76,35.01 56.76,36.28 57.78,37.3 60.83,37.3 61.34,37.81 61.34,40.6 60.83,41.11 U$9.P$2
N$96
  Bottom 0.406: R21.1 126.36,64.22 128.14,62.45 128.14,60.67 127.63,60.16 125.34,60.16 125.09,59.91 125.09,58.13 125.6,57.62 LED5.A
N$97
  Bottom 0.406: T3.2 125.09,54.06 126.11,55.08 LED5.K
N$98
  Top 0.406: R22.2 141.6,75.65 142.33,76.38 U$13.P$2
N$99
  Top 0.406: U$10.P$11 37.97,30.95 39.24,32.22 39.24,34 40,34.76 42.79,34.76 43.81,35.52 43.81,63.97 45.33,65.49 87.5,65.49 88.26,66.26 MEGA16.33
  Bottom 0.406: U$10.P$10 U$10.P$11
N$100
  Bottom 0.406: RAN1.2.2 24.76,24.6 U$10.P$8
N$101
  Bottom 0.406: RAN1.1.E 31.11,15.71 29.33,17.49 29.33,20.28 31.11,22.06 31.11,25.36 31.36,25.62 U$10.P$9
N$102
  Bottom 0.406: RAN1.1.S 25.39,11.27 RAN1.2.1
N$103
  Bottom 0.406: R39.1 19.93,33.49 21.2,34.76 21.2,36.79 21.71,37.3 25.01,37.3 25.78,38.06 25.78,40.35 25.01,41.11 U$10.P$2
N$104
  Bottom 0.406: T4.1 140.33,58.89 141.6,60.16 R22.1 141.6,69.3 144.14,71.84 R25.2
N$105
  Bottom 0.406: R26.1 136.52,63.97 T4.2
N$106
  Bottom 0.406: LED6.A R25.1
N$107
  Bottom 0.406: SV4.7 93.34,90.64 89.53,90.64 88.26,89.37 MEGA16.8
N$108
  Bottom 0.406: SV4.1 88.26,91.91 86.74,90.39 85.47,90.39 84.45,89.37 84.45,86.83 85.72,85.56 92.07,85.56 93.34,86.83 MEGA16.6
N$109
  Bottom 0.406: SV4.9 97.91,93.18 96.39,91.66 95.63,91.66 93.85,89.88 91.05,89.88 90.8,89.62 MEGA16.7 90.8,87.85
N$110
  Top 0.406: R29.1 141.6,62.7 141.6,60.16 LED7.A
N$111
  Bottom 0.406: T6.2 137.79,54.06 138.81,55.08 LED7.K
N$112
  Bottom 0.406: R36.1 26.03,16.98 26.03,32.73 25.27,33.49 U$10.P$5
N$113
  Bottom 0.406: R8.1 37.46,13.68 44.06,20.28 44.06,32.47 43.05,33.49 U$3.P$5
N$114
  Bottom 0.406: U$4.P$5 151,33.49 152.27,34.76 156.84,34.76 157.6,34 157.6,27.9 156.84,27.14 154.3,27.14 153.28,26.12 153.28,21.55 144.14,12.41 R12.1
N$115
  Bottom 0.406: R16.1 126.36,13.42 132.71,19.77 132.71,32.47 131.69,33.49 U$5.P$5 129.92,33.49
N$116
  Bottom 0.406: R20.1 108.58,13.68 114.93,20.03 114.93,32.47 113.91,33.49 U$6.P$5
N$117
  Bottom 0.406: R24.1 90.8,13.42 97.15,19.77 97.15,32.47 96.13,33.49 94.86,33.49 94.61,33.24 U$7.P$5
N$118
  Bottom 0.406: R28.1 73.02,13.42 79.37,19.77 79.37,32.22 78.1,33.49 U$8.P$5
N$119
  Bottom 0.406: R32.1 55.24,13.42 61.84,20.03 61.84,32.22 60.57,33.49 U$9.P$5
N$120
  Bottom 0.406: LED2.A R10.1
N$121
  Bottom 0.406: R33.1 113.66,63.97 115.44,62.19 115.44,61.43 114.17,60.16 112.9,60.16 112.39,59.65 112.39,58.38 113.15,57.62 LED3.A
N$122
  Bottom 0.406: R30.2 154.3,77.43 154.81,77.94 154.81,79.97 155.06,80.23 155.03,80.26 U$14.P$2
N$123
  Top 0.406: R30.1 154.3,66 153.54,66.76 150.74,66.76 150.49,66.51 150.49,64.22 151.51,63.21 152.52,63.21 153.28,62.45 153.28,60.16 152.01,58.89 T7.1
  Bottom 0.406: R34.2 156.59,75.4 154.3,73.11 R30.1
N$124
  Bottom 0.406: R37.1 149.22,63.97 T7.2
N$125
  Bottom 0.406: LED8.A R34.1
N$126
  Top 0.406: R38.1 154.3,62.7 154.3,60.16 LED9.A
N$127
  Top 0.406: LED9.K 156.84,53.56 155.57,52.29 152.01,52.29 T8.2
N$128
  Top 0.406: LED10.A 86.99,68.54 86.99,74.64 95.88,83.53 MEGA16.5
N$129
  Top 0.406: LED10.K R40.2
V+
  Top 0.406: SV2.18 3.42,83.02 2.92,82.51 2.92,53.3 3.68,52.54 4.19,52.54 4.44,52.29 SV1.14
  Bottom 0.406: SV1.8 SV1.7 10.79,48.73 11.3,48.73 12.06,49.49 12.06,51.78 11.3,52.54 6.73,52.54 | 6.73,52.54 SV1.14 | 6.73,52.54 SV1.13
